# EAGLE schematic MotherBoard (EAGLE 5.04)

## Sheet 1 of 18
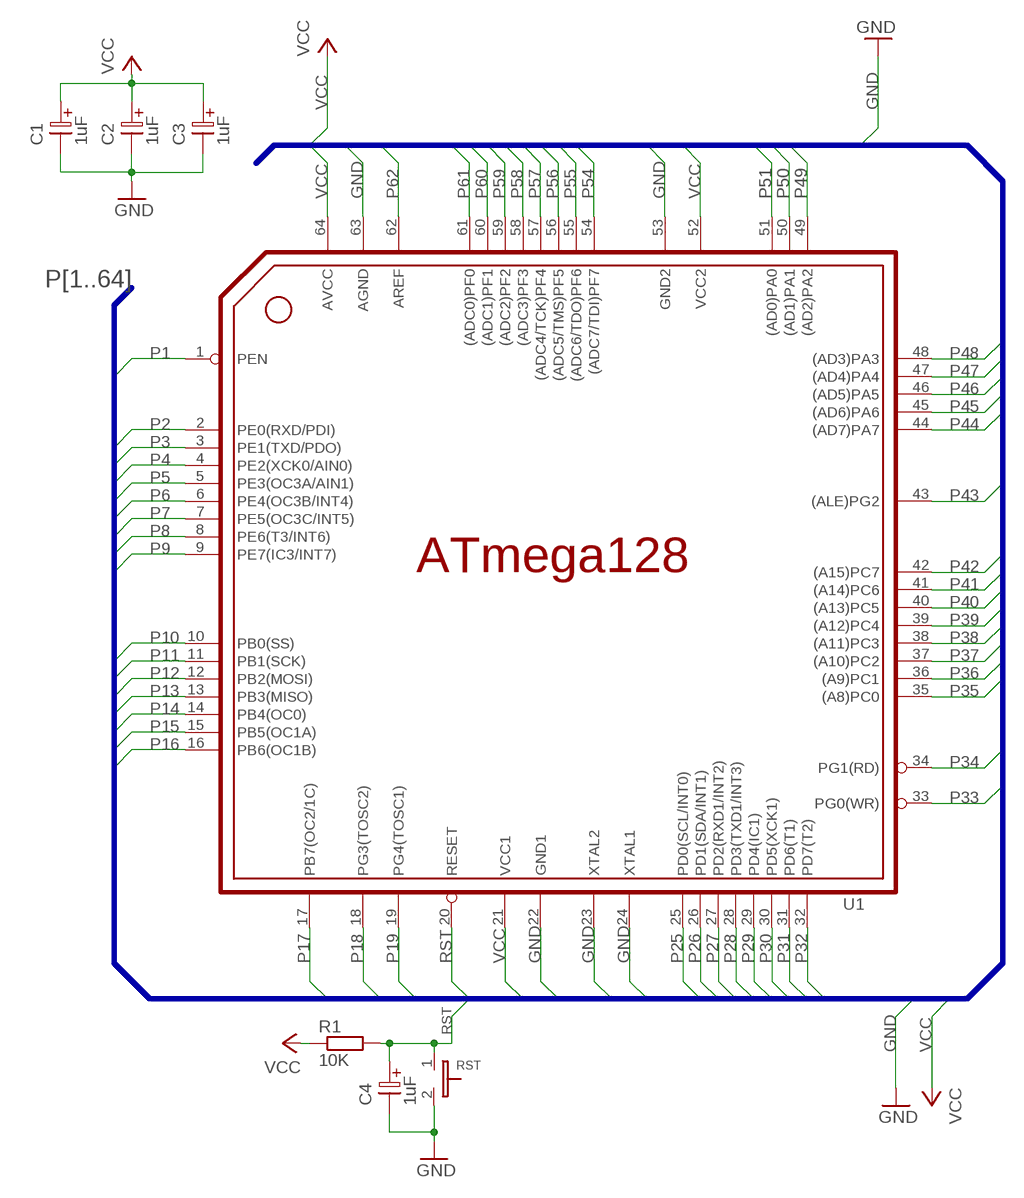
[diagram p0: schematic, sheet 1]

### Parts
C1  1uF  ELC2.5  [ELC2.5]
C2  1uF  ELC2.5  [ELC2.5]
C3  1uF  ELC2.5  [ELC2.5]
C4  1uF  ELC2.5  [ELC2.5]
R1  10K  R-5-10M  [R-10]
RST  TAC_SW_S  [SW]
U1  ATMEGA128_HOLDERH  [HEADER64PIN]

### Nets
GND: C1.2 C2.2 C3.2 C4.2 RST.2 U1.22(GND1) U1.23(XTAL2) U1.24(XTAL1) U1.53(GND2) U1.63(AGND) ; also sheet 2,3,4,5,6,7,8,10,11,12,13,14,15,16,17,18
P1: U1.1(PEN)
P2: U1.2(PE0(RXD/PDI)) ; also sheet 4,6,11,12
P3: U1.3(PE1(TXD/PDO)) ; also sheet 4,6,11,12
P4: U1.4(PE2(XCK0/AIN0)) ; also sheet 4,6,11,12
P5: U1.5(PE3(OC3A/AIN1)) ; also sheet 4,6,12,18
P6: U1.6(PE4(OC3B/INT4)) ; also sheet 4,5,12
P7: U1.7(PE5(OC3C/INT5)) ; also sheet 4,5,12
P8: U1.8(PE6(T3/INT6)) ; also sheet 4,5,12
P9: U1.9(PE7(IC3/INT7)) ; also sheet 4,5,12
P10: U1.10(PB0(SS)) ; also sheet 4,5,16
P11: U1.11(PB1(SCK)) ; also sheet 3,4,5,16
P12: U1.12(PB2(MOSI)) ; also sheet 3,4,5,16
P13: U1.13(PB3(MISO)) ; also sheet 3,4,5,16
P14: U1.14(PB4(OC0)) ; also sheet 4,5,13
P15: U1.15(PB5(OC1A)) ; also sheet 4,5,15
P16: U1.16(PB6(OC1B)) ; also sheet 4,5,18
P17: U1.17(PB7(OC2/1C)) ; also sheet 4,5,15
P18: U1.18(PG3(TOSC2))
P19: U1.19(PG4(TOSC1))
P25: U1.25(PD0(SCL/INT0)) ; also sheet 4,5,8,16
P26: U1.26(PD1(SDA/INT1)) ; also sheet 4,5,8
P27: U1.27(PD2(RXD1/INT2)) ; also sheet 4,5,6,8
P28: U1.28(PD3(TXD1/INT3)) ; also sheet 4,5,6,8
P29: U1.29(PD4(IC1)) ; also sheet 4,18
P30: U1.30(PD5(XCK1)) ; also sheet 4,18
P31: U1.31(PD6(T1)) ; also sheet 4,18
P32: U1.32(PD7(T2)) ; also sheet 4,18
P33: U1.33(PG0(WR)) ; also sheet 10,17
P34: U1.34(PG1(RD)) ; also sheet 10,17
P35: U1.35((A8)PC0) ; also sheet 4,10,13
P36: U1.36((A9)PC1) ; also sheet 4,10
P37: U1.37((A10)PC2) ; also sheet 4,7,10
P38: U1.38((A11)PC3) ; also sheet 4,7,10
P39: U1.39((A12)PC4) ; also sheet 4,7,9,10
P40: U1.40((A13)PC5) ; also sheet 4,7,9,10
P41: U1.41((A14)PC6) ; also sheet 4,7,9,10
P42: U1.42((A15)PC7) ; also sheet 4,7,9,10
P43: U1.43((ALE)PG2) ; also sheet 13,16
P44: U1.44((AD7)PA7) ; also sheet 4,7,9
P45: U1.45((AD6)PA6) ; also sheet 4,7,9
P46: U1.46((AD5)PA5) ; also sheet 4,7,9
P47: U1.47((AD4)PA4) ; also sheet 4,7,9,17
P48: U1.48((AD3)PA3) ; also sheet 4,7,9,17
P49: U1.49((AD2)PA2) ; also sheet 4,7,9,17
P50: U1.50((AD1)PA1) ; also sheet 4,6,7,9
P51: U1.51((AD0)PA0) ; also sheet 4,6,7,9
P54: U1.54((ADC7/TDI)PF7) ; also sheet 4,13
P55: U1.55((ADC6/TDO)PF6) ; also sheet 4,13
P56: U1.56((ADC5/TMS)PF5) ; also sheet 4,13
P57: U1.57((ADC4/TCK)PF4) ; also sheet 4,13
P58: U1.58((ADC3)PF3) ; also sheet 4,13
P59: U1.59((ADC2)PF2) ; also sheet 4,13
P60: U1.60((ADC1)PF1) ; also sheet 4,13
P61: U1.61((ADC0)PF0) ; also sheet 4,13
P62: U1.62(AREF) ; also sheet 13
RST: C4.1 R1.2 RST.1 U1.20(RESET) ; also sheet 3
VCC: C1.1 C2.1 C3.1 R1.1 U1.21(VCC1) U1.52(VCC2) U1.64(AVCC) ; also sheet 2,3,4,5,6,7,8,9,10,11,12,13,14,15,16,17,18

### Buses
P[1..64]

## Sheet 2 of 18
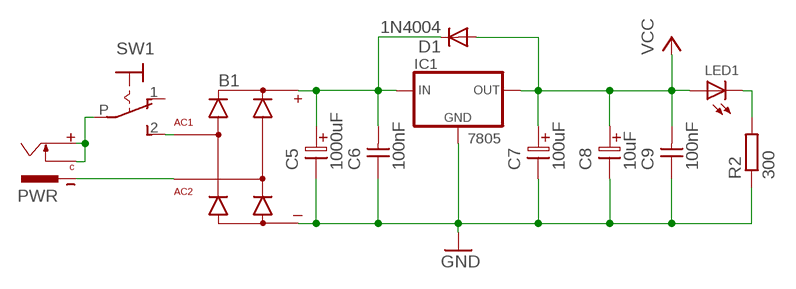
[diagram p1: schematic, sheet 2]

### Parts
B1  RB1A  [RB1A]
C5  1000uF  ELC5  [ELC5]
C6  100nF  CAP2.5  [CAP2.5]
C7  100uF  ELC2.5  [ELC2.5]
C8  10uF  ELC2.5  [ELC2.5]
C9  100nF  CAP2.5  [CAP2.5]
D1  1N4004  [DO41-10]
IC1  7805  78XXL  [78XXL]
LED1  LED3  [LED3MM]
PWR  DC-JACK.  [PW]
R2  300  RESISTOR-7M  [R-7]
SW1  POWER_SWSW  [SWITCH]

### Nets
GND: B1.- C5.2 C6.1 C7.2 C8.2 C9.1 IC1.GND R2.1 ; also sheet 1,3,4,5,6,7,8,10,11,12,13,14,15,16,17,18
N$2: B1.AC2 PWR.-
N$3: B1.+ C5.1 C6.2 D1.C IC1.IN
N$4: LED1.K(C) R2.2
N$189: B1.AC1 SW1.2
N$192: PWR.+ PWR.C SW1.P
VCC: C7.1 C8.1 C9.2 D1.A IC1.OUT LED1.A ; also sheet 1,3,4,5,6,7,8,9,10,11,12,13,14,15,16,17,18
Unconnected: SW1.1

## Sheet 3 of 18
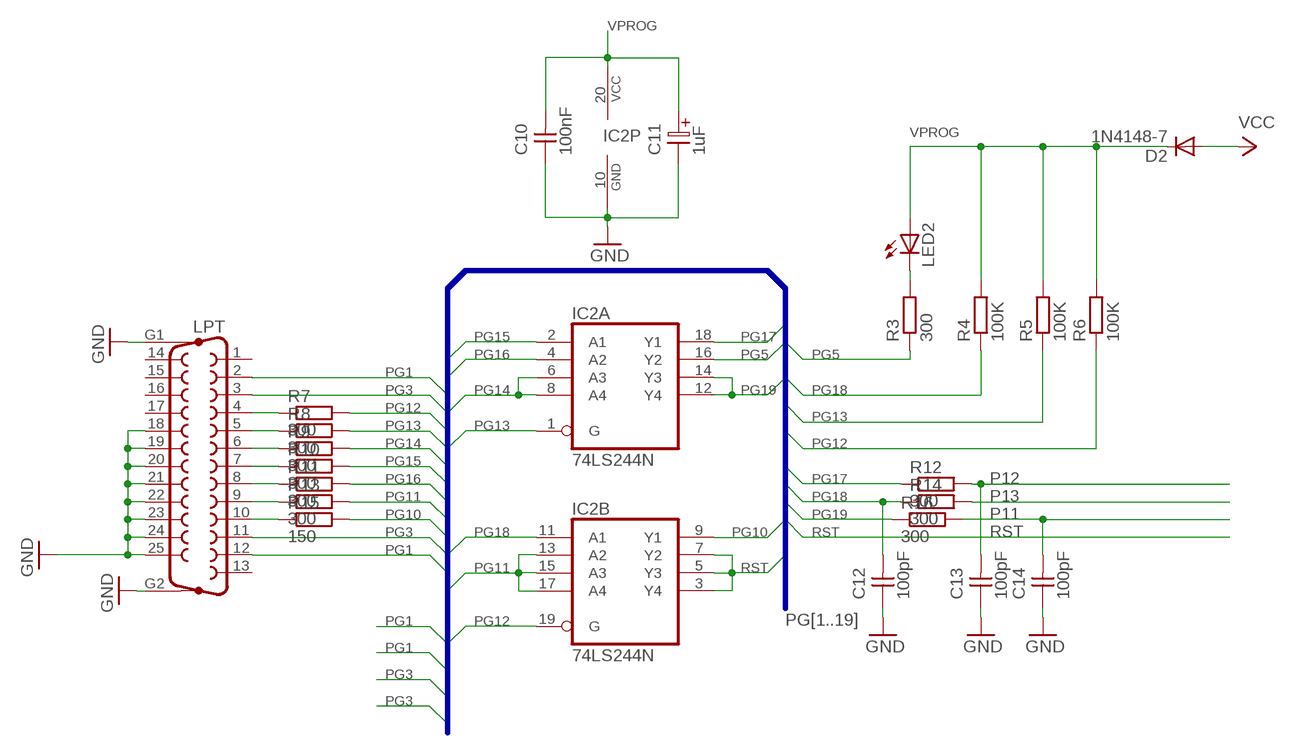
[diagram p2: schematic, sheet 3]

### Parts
C10  100nF  CAP2.5  [CAP2.5]
C11  1uF  ELC2.5  [ELC2.5]
C12  100pF  CAP2.5  [CAP2.5]
C13  100pF  CAP2.5  [CAP2.5]
C14  100pF  CAP2.5  [CAP2.5]
D2  1N4148-7  [DO35-7]
IC2  74LS244N  [DIL20]
LED2  LED3MM  [LED3MM]
LPT  F25HP  [F25HP]
R3  300  R-5-10M  [R-10]
R4  100K  R-5-10M  [R-10]
R5  100K  R-5-10M  [R-10]
R6  100K  R-5-10M  [R-10]
R7  300  R-5-10M  [R-10]
R8  300  R-5-10M  [R-10]
R9  300  R-5-10M  [R-10]
R10  300  R-5-10M  [R-10]
R11  300  R-5-10M  [R-10]
R12  300  R-5-10M  [R-10]
R13  300  R-5-10M  [R-10]
R14  300  R-5-10M  [R-10]
R15  150  R-5-10M  [R-10]
R16  300  R-5-10M  [R-10]

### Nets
GND: C10.1 C11.2 C12.1 C13.1 C14.1 IC2.10(P:GND) LPT.18 LPT.19 LPT.20 LPT.21 LPT.22 LPT.23 LPT.24 LPT.25 LPT.G1 LPT.G2 ; also sheet 1,2,4,5,6,7,8,10,11,12,13,14,15,16,17,18
N$5: LED2.K(C) R3.2
N$265: LPT.4 R7.1
N$266: LPT.5 R8.1
N$278: LPT.6 R9.1
N$279: LPT.7 R10.1
N$280: LPT.8 R11.1
N$281: LPT.9 R13.1
N$282: LPT.10 R15.1
P11: C14.2 R16.2 ; also sheet 1,4,5,16
P12: C13.2 R12.2 ; also sheet 1,4,5,16
P13: R14.2 ; also sheet 1,4,5,16
PG1: LPT.2 LPT.12
PG3: LPT.3 LPT.11
PG5: IC2.16(A:Y2) R3.1
PG10: IC2.9(B:Y1) R15.2
PG11: IC2.13(B:A2) IC2.15(B:A3) IC2.17(B:A4) R13.2
PG12: IC2.19(B:G) R6.1 R7.2
PG13: IC2.1(A:G) R5.1 R8.2
PG14: IC2.6(A:A3) IC2.8(A:A4) R9.2
PG15: IC2.2(A:A1) R10.2
PG16: IC2.4(A:A2) R11.2
PG17: IC2.18(A:Y1) R12.1
PG18: C12.2 IC2.11(B:A1) R4.1 R14.1
PG19: IC2.12(A:Y4) IC2.14(A:Y3) R16.1
RST: IC2.3(B:Y4) IC2.5(B:Y3) IC2.7(B:Y2) ; also sheet 1
VCC: D2.A ; also sheet 1,2,4,5,6,7,8,9,10,11,12,13,14,15,16,17,18
VPROG: C10.2 C11.1 D2.C IC2.20(P:VCC) LED2.A R4.2 R5.2 R6.2
Unconnected: LPT.1 LPT.13 LPT.14 LPT.15 LPT.16 LPT.17

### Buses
PG[1..19]

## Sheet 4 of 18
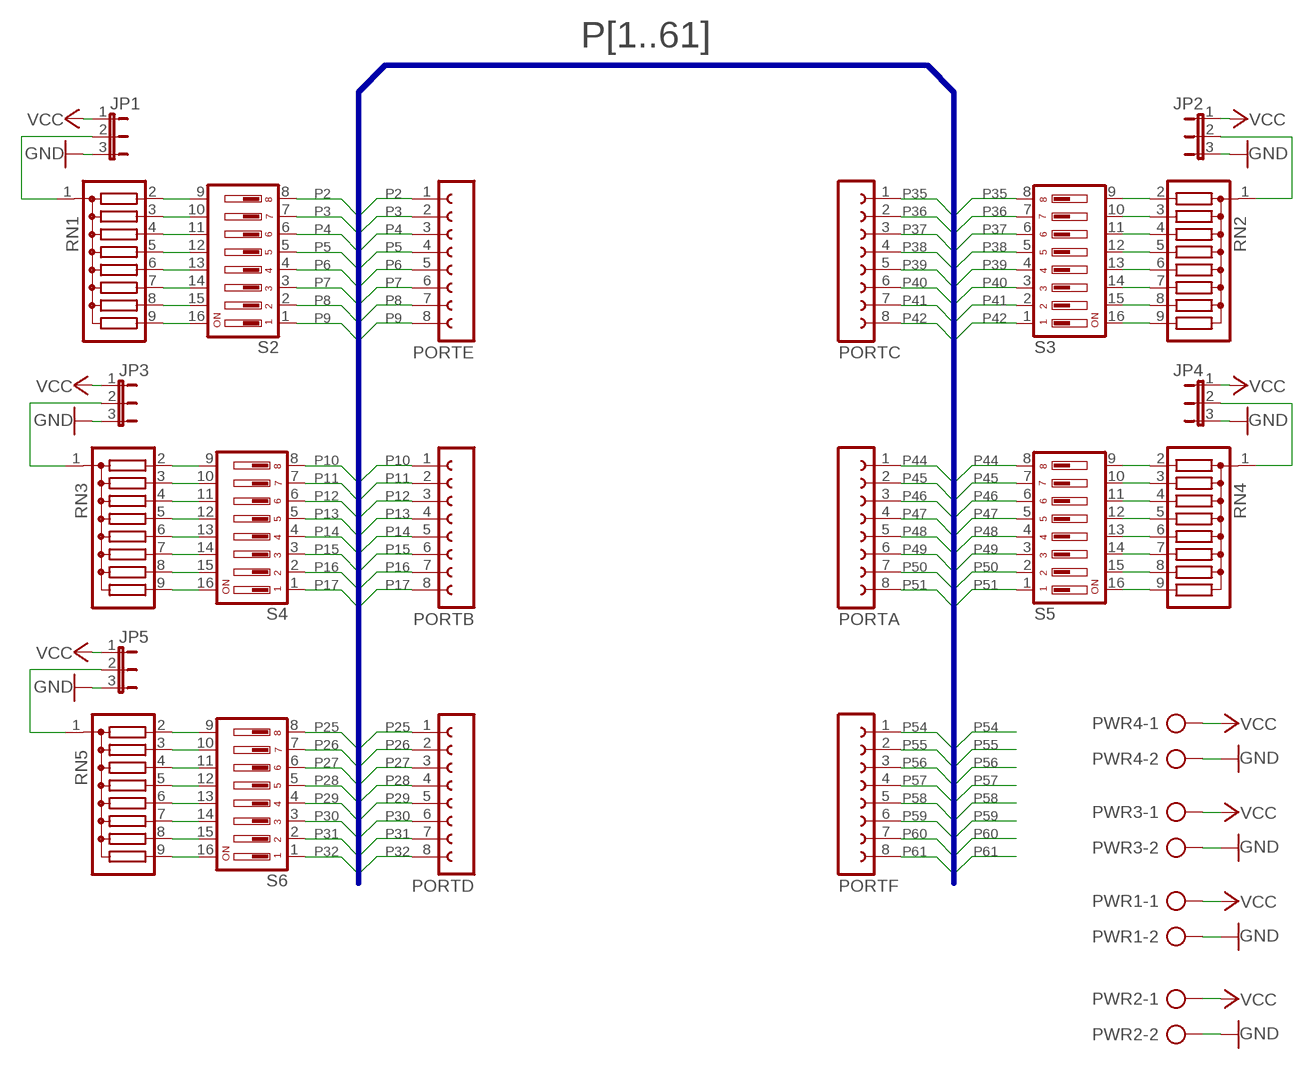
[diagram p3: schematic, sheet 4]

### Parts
JP1  JP2E  [JP2]
JP2  JP2E  [JP2]
JP3  JP2E  [JP2]
JP4  JP2E  [JP2]
JP5  JP2E  [JP2]
PORTA  FE08-1  [FE08]
PORTB  FE08-1  [FE08]
PORTC  FE08-1  [FE08]
PORTD  FE08-1  [FE08]
PORTE  FE08-1  [FE08]
PORTF  FE08-1  [FE08]
PWR1  AK500/2  [AK500/2]
PWR2  AK500/2  [AK500/2]
PWR3  AK500/2  [AK500/2]
PWR4  AK500/2  [AK500/2]
RN1  G08R  [SIL9]
RN2  G08R  [SIL9]
RN3  G08R  [SIL9]
RN4  G08R  [SIL9]
RN5  G08R  [SIL9]
S2  DIP08YL  [DIP08YL]
S3  DIP08YL  [DIP08YL]
S4  DIP08YL  [DIP08YL]
S5  DIP08YL  [DIP08YL]
S6  DIP08YL  [DIP08YL]

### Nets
GND: JP1.3 JP2.3 JP3.3 JP4.3 JP5.3 PWR1.2 PWR2.2 PWR3.2 PWR4.2 ; also sheet 1,2,3,5,6,7,8,10,11,12,13,14,15,16,17,18
N$6: JP1.2 RN1.1
N$7: JP3.2 RN3.1
N$8: RN3.2 S4.9
N$12: RN1.2 S2.9
N$13: RN1.3 S2.10
N$14: RN1.4 S2.11
N$15: RN1.5 S2.12
N$16: RN1.6 S2.13
N$17: RN1.7 S2.14
N$18: RN1.8 S2.15
N$19: RN1.9 S2.16
N$20: RN3.3 S4.10
N$21: RN3.4 S4.11
N$22: RN3.5 S4.12
N$23: RN3.6 S4.13
N$24: RN3.7 S4.14
N$25: RN3.8 S4.15
N$26: RN3.9 S4.16
N$27: JP5.2 RN5.1
N$28: RN5.2 S6.9
N$29: RN5.3 S6.10
N$30: RN5.4 S6.11
N$31: RN5.5 S6.12
N$32: RN5.6 S6.13
N$33: RN5.7 S6.14
N$34: RN5.8 S6.15
N$35: RN5.9 S6.16
N$42: JP4.2 RN4.1
N$43: RN4.2 S5.9
N$44: RN4.3 S5.10
N$45: RN4.4 S5.11
N$46: RN4.5 S5.12
N$47: RN4.6 S5.13
N$48: RN4.7 S5.14
N$49: RN4.8 S5.15
N$50: RN4.9 S5.16
N$51: JP2.2 RN2.1
N$52: RN2.2 S3.9
N$53: RN2.3 S3.10
N$54: RN2.4 S3.11
N$55: RN2.5 S3.12
N$56: RN2.6 S3.13
N$57: RN2.7 S3.14
N$58: RN2.8 S3.15
N$59: RN2.9 S3.16
P2: PORTE.1 S2.8 ; also sheet 1,6,11,12
P3: PORTE.2 S2.7 ; also sheet 1,6,11,12
P4: PORTE.3 S2.6 ; also sheet 1,6,11,12
P5: PORTE.4 S2.5 ; also sheet 1,6,12,18
P6: PORTE.5 S2.4 ; also sheet 1,5,12
P7: PORTE.6 S2.3 ; also sheet 1,5,12
P8: PORTE.7 S2.2 ; also sheet 1,5,12
P9: PORTE.8 S2.1 ; also sheet 1,5,12
P10: PORTB.1 S4.8 ; also sheet 1,5,16
P11: PORTB.2 S4.7 ; also sheet 1,3,5,16
P12: PORTB.3 S4.6 ; also sheet 1,3,5,16
P13: PORTB.4 S4.5 ; also sheet 1,3,5,16
P14: PORTB.5 S4.4 ; also sheet 1,5,13
P15: PORTB.6 S4.3 ; also sheet 1,5,15
P16: PORTB.7 S4.2 ; also sheet 1,5,18
P17: PORTB.8 S4.1 ; also sheet 1,5,15
P25: PORTD.1 S6.8 ; also sheet 1,5,8,16
P26: PORTD.2 S6.7 ; also sheet 1,5,8
P27: PORTD.3 S6.6 ; also sheet 1,5,6,8
P28: PORTD.4 S6.5 ; also sheet 1,5,6,8
P29: PORTD.5 S6.4 ; also sheet 1,18
P30: PORTD.6 S6.3 ; also sheet 1,18
P31: PORTD.7 S6.2 ; also sheet 1,18
P32: PORTD.8 S6.1 ; also sheet 1,18
P35: PORTC.1 S3.8 ; also sheet 1,10,13
P36: PORTC.2 S3.7 ; also sheet 1,10
P37: PORTC.3 S3.6 ; also sheet 1,7,10
P38: PORTC.4 S3.5 ; also sheet 1,7,10
P39: PORTC.5 S3.4 ; also sheet 1,7,9,10
P40: PORTC.6 S3.3 ; also sheet 1,7,9,10
P41: PORTC.7 S3.2 ; also sheet 1,7,9,10
P42: PORTC.8 S3.1 ; also sheet 1,7,9,10
P44: PORTA.1 S5.8 ; also sheet 1,7,9
P45: PORTA.2 S5.7 ; also sheet 1,7,9
P46: PORTA.3 S5.6 ; also sheet 1,7,9
P47: PORTA.4 S5.5 ; also sheet 1,7,9,17
P48: PORTA.5 S5.4 ; also sheet 1,7,9,17
P49: PORTA.6 S5.3 ; also sheet 1,7,9,17
P50: PORTA.7 S5.2 ; also sheet 1,6,7,9
P51: PORTA.8 S5.1 ; also sheet 1,6,7,9
P54: PORTF.1 ; also sheet 1,13
P55: PORTF.2 ; also sheet 1,13
P56: PORTF.3 ; also sheet 1,13
P57: PORTF.4 ; also sheet 1,13
P58: PORTF.5 ; also sheet 1,13
P59: PORTF.6 ; also sheet 1,13
P60: PORTF.7 ; also sheet 1,13
P61: PORTF.8 ; also sheet 1,13
VCC: JP1.1 JP2.1 JP3.1 JP4.1 JP5.1 PWR1.1 PWR2.1 PWR3.1 PWR4.1 ; also sheet 1,2,3,5,6,7,8,9,10,11,12,13,14,15,16,17,18

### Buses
P[1..61]

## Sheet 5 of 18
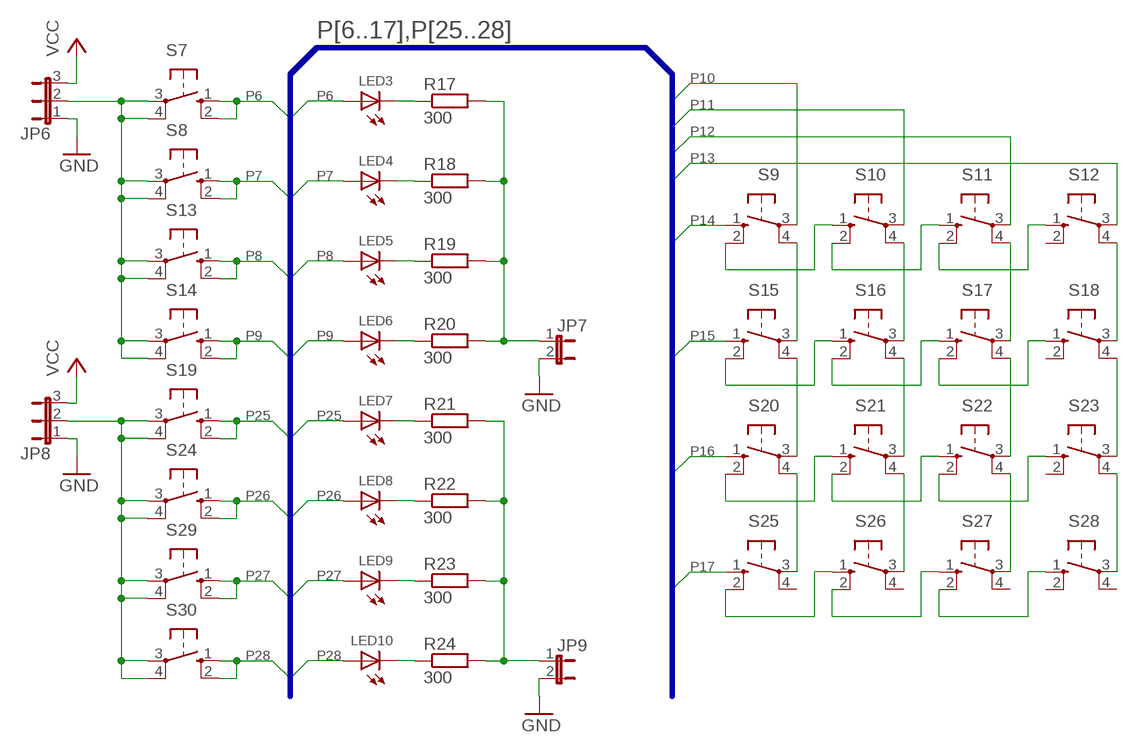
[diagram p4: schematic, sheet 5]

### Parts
JP6  JP2E  [JP2]
JP7  JP1EY  [JP1Y]
JP8  JP2E  [JP2]
JP9  JP1EY  [JP1Y]
LED3  LED5  [LED5MM]
LED4  LED5  [LED5MM]
LED5  LED5  [LED5MM]
LED6  LED5  [LED5MM]
LED7  LED5  [LED5MM]
LED8  LED5  [LED5MM]
LED9  LED5  [LED5MM]
LED10  LED5  [LED5MM]
R17  300  RESISTOR-10M  [R-10]
R18  300  RESISTOR-10M  [R-10]
R19  300  RESISTOR-10M  [R-10]
R20  300  RESISTOR-10M  [R-10]
R21  300  RESISTOR-8M  [R-8]
R22  300  RESISTOR-8M  [R-8]
R23  300  RESISTOR-8M  [R-8]
R24  300  RESISTOR-8M  [R-8]
S7  10-XX  [B3F-10XX]
S8  10-XX  [B3F-10XX]
S9  TAC_SW_B  [B3F-40XX]
S10  TAC_SW_B  [B3F-40XX]
S11  TAC_SW_B  [B3F-40XX]
S12  TAC_SW_B  [B3F-40XX]
S13  10-XX  [B3F-10XX]
S14  10-XX  [B3F-10XX]
S15  TAC_SW_B  [B3F-40XX]
S16  TAC_SW_B  [B3F-40XX]
S17  TAC_SW_B  [B3F-40XX]
S18  TAC_SW_B  [B3F-40XX]
S19  10-XX  [B3F-10XX]
S20  TAC_SW_B  [B3F-40XX]
S21  TAC_SW_B  [B3F-40XX]
S22  TAC_SW_B  [B3F-40XX]
S23  TAC_SW_B  [B3F-40XX]
S24  10-XX  [B3F-10XX]
S25  TAC_SW_B  [B3F-40XX]
S26  TAC_SW_B  [B3F-40XX]
S27  TAC_SW_B  [B3F-40XX]
S28  TAC_SW_B  [B3F-40XX]
S29  10-XX  [B3F-10XX]
S30  10-XX  [B3F-10XX]

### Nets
GND: JP6.1 JP7.2 JP8.1 JP9.2 ; also sheet 1,2,3,4,6,7,8,10,11,12,13,14,15,16,17,18
N$9: JP6.2 S7.3(P) S7.4(P1) S8.3(P) S8.4(P1) S13.3(P) S13.4(P1) S14.3(P) S14.4(P1)
N$11: JP8.2 S19.3(P) S19.4(P1) S24.3(P) S24.4(P1) S29.3(P) S29.4(P1) S30.3(P) S30.4(P1)
N$36: S9.2(S1) S10.1(S)
N$37: S10.2(S1) S11.1(S)
N$38: S11.2(S1) S12.1(S)
N$39: S20.2(S1) S21.1(S)
N$40: S21.2(S1) S22.1(S)
N$41: S22.2(S1) S23.1(S)
N$60: S15.2(S1) S16.1(S)
N$61: S16.2(S1) S17.1(S)
N$62: S17.2(S1) S18.1(S)
N$65: S25.2(S1) S26.1(S)
N$66: S26.2(S1) S27.1(S)
N$67: S9.4(P1) S15.3(P)
N$68: S10.4(P1) S16.3(P)
N$69: S11.4(P1) S17.3(P)
N$70: S12.4(P1) S18.3(P)
N$71: S27.2(S1) S28.1(S)
N$73: S20.4(P1) S25.3(P)
N$74: S21.4(P1) S26.3(P)
N$75: S22.4(P1) S27.3(P)
N$76: S23.4(P1) S28.3(P)
N$77: S15.4(P1) S20.3(P)
N$78: S16.4(P1) S21.3(P)
N$79: S17.4(P1) S22.3(P)
N$80: S18.4(P1) S23.3(P)
N$138: LED3.K(C) R17.1
N$139: LED5.K(C) R19.1
N$140: LED6.K(C) R20.1
N$141: LED7.K(C) R21.1
N$142: LED8.K(C) R22.1
N$143: LED9.K(C) R23.1
N$144: LED10.K(C) R24.1
N$145: LED4.K(C) R18.1
N$276: JP7.1 R17.2 R18.2 R19.2 R20.2
N$277: JP9.1 R21.2 R22.2 R23.2 R24.2
P6: LED3.A S7.1(S) S7.2(S1) ; also sheet 1,4,12
P7: LED4.A S8.1(S) S8.2(S1) ; also sheet 1,4,12
P8: LED5.A S13.1(S) S13.2(S1) ; also sheet 1,4,12
P9: LED6.A S14.1(S) S14.2(S1) ; also sheet 1,4,12
P10: S9.3(P) ; also sheet 1,4,16
P11: S10.3(P) ; also sheet 1,3,4,16
P12: S11.3(P) ; also sheet 1,3,4,16
P13: S12.3(P) ; also sheet 1,3,4,16
P14: S9.1(S) ; also sheet 1,4,13
P15: S15.1(S) ; also sheet 1,4,15
P16: S20.1(S) ; also sheet 1,4,18
P17: S25.1(S) ; also sheet 1,4,15
P25: LED7.A S19.1(S) S19.2(S1) ; also sheet 1,4,8,16
P26: LED8.A S24.1(S) S24.2(S1) ; also sheet 1,4,8
P27: LED9.A S29.1(S) S29.2(S1) ; also sheet 1,4,6,8
P28: LED10.A S30.1(S) S30.2(S1) ; also sheet 1,4,6,8
VCC: JP6.3 JP8.3 ; also sheet 1,2,3,4,6,7,8,9,10,11,12,13,14,15,16,17,18
Unconnected: S12.2(S1) S18.2(S1) S23.2(S1) S25.4(P1) S26.4(P1) S27.4(P1) S28.2(S1) S28.4(P1)

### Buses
P[6..17],P[25..28]

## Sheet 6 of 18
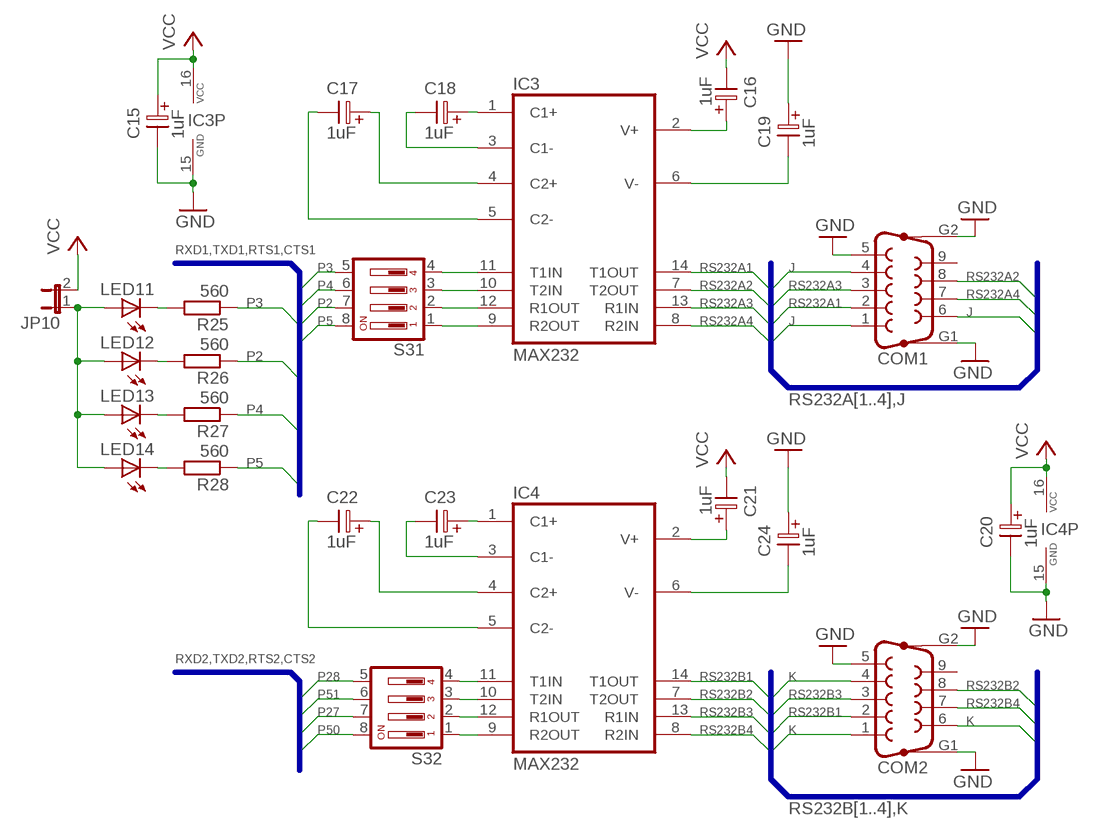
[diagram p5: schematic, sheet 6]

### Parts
C15  1uF  ELC2.5  [ELC2.5]
C16  1uF  ELC2.5  [ELC2.5]
C17  1uF  ELC2.5  [ELC2.5]
C18  1uF  ELC2.5  [ELC2.5]
C19  1uF  ELC2.5  [ELC2.5]
C20  1uF  ELC2.5  [ELC2.5]
C21  1uF  ELC2.5  [ELC2.5]
C22  1uF  ELC2.5  [ELC2.5]
C23  1uF  ELC2.5  [ELC2.5]
C24  1uF  ELC2.5  [ELC2.5]
COM1  F09HP  [F09HP]
COM2  F09HP  [F09HP]
IC3  MAX232  [DIL16L]
IC4  MAX232  [DIL16L]
JP10  JP1EY  [JP1Y]
LED11  LED3MM  [LED3MM]
LED12  LED3MM  [LED3MM]
LED13  LED3MM  [LED3MM]
LED14  LED3MM  [LED3MM]
R25  560  R-5-10M  [R-10]
R26  560  R-5-10M  [R-10]
R27  560  R-5-10M  [R-10]
R28  560  R-5-10M  [R-10]
S31  DIP04YL  [DIP04YL]
S32  DIP04YL  [DIP04YL]

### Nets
GND: C15.2 C19.1 C20.2 C24.1 COM1.5 COM1.G1 COM1.G2 COM2.5 COM2.G1 COM2.G2 IC3.15(GND) IC4.15(GND) ; also sheet 1,2,3,4,5,7,8,10,11,12,13,14,15,16,17,18
J: COM1.1 COM1.4 COM1.6
K: COM2.1 COM2.4 COM2.6
N$10: C18.1 IC3.1(C1+)
N$63: C18.2 IC3.3(C1-)
N$64: C17.1 IC3.4(C2+)
N$72: C17.2 IC3.5(C2-)
N$81: C19.2 IC3.6(V-)
N$82: C16.1 IC3.2(V+)
N$83: IC3.9(R2OUT) S31.1
N$84: IC3.12(R1OUT) S31.2
N$85: IC3.10(T2IN) S31.3
N$86: IC3.11(T1IN) S31.4
N$87: C23.1 IC4.1(C1+)
N$88: C23.2 IC4.3(C1-)
N$89: C22.1 IC4.4(C2+)
N$90: C22.2 IC4.5(C2-)
N$91: C24.2 IC4.6(V-)
N$92: C21.1 IC4.2(V+)
N$93: IC4.9(R2OUT) S32.1
N$94: IC4.12(R1OUT) S32.2
N$95: IC4.10(T2IN) S32.3
N$96: IC4.11(T1IN) S32.4
N$97: LED11.K(C) R25.2
N$230: JP10.1 LED11.A LED12.A LED13.A LED14.A
N$269: LED12.K(C) R26.2
N$270: LED13.K(C) R27.2
N$271: LED14.K(C) R28.2
P2: R26.1 S31.7 ; also sheet 1,4,11,12
P3: R25.1 S31.5 ; also sheet 1,4,11,12
P4: R27.1 S31.6 ; also sheet 1,4,11,12
P5: R28.1 S31.8 ; also sheet 1,4,12,18
P27: S32.7 ; also sheet 1,4,5,8
P28: S32.5 ; also sheet 1,4,5,8
P50: S32.8 ; also sheet 1,4,7,9
P51: S32.6 ; also sheet 1,4,7,9
RS232A1: COM1.2 IC3.14(T1OUT)
RS232A2: COM1.8 IC3.7(T2OUT)
RS232A3: COM1.3 IC3.13(R1IN)
RS232A4: COM1.7 IC3.8(R2IN)
RS232B1: COM2.2 IC4.14(T1OUT)
RS232B2: COM2.8 IC4.7(T2OUT)
RS232B3: COM2.3 IC4.13(R1IN)
RS232B4: COM2.7 IC4.8(R2IN)
VCC: C15.1 C16.2 C20.1 C21.2 IC3.16(VCC) IC4.16(VCC) JP10.2 ; also sheet 1,2,3,4,5,7,8,9,10,11,12,13,14,15,16,17,18
Unconnected: COM1.9 COM2.9

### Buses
RS232A[1..4],J
RXD1,TXD1,RTS1,CTS1
RS232B[1..4],K
RXD2,TXD2,RTS2,CTS2

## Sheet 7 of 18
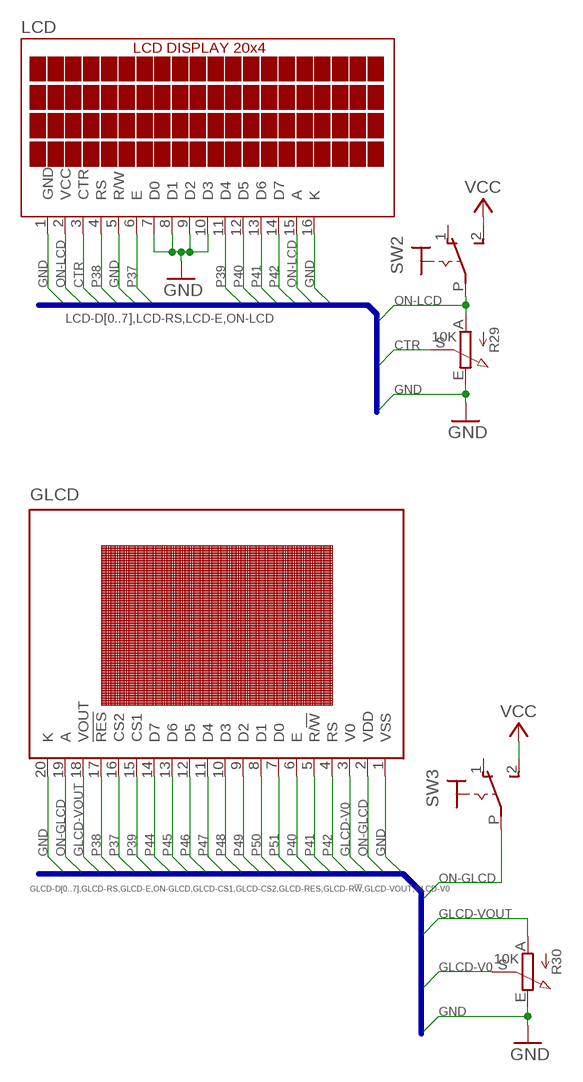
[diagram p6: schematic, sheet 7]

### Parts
GLCD  LCD128X64  [LCD128X64]
LCD  LCD20X4  [LCD20X4]
R29  10K  POT  [POT]
R30  10K  POT  [POT]
SW2  POWER_SW3  [ON_OFF]
SW3  POWER_SW3  [ON_OFF]

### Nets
CTR: LCD.3(CTR) R29.S
GLCD-V0: GLCD.3(V0) R30.S
GLCD-VOUT: GLCD.18(VOUT) R30.A
GND: GLCD.1(VSS) GLCD.20(K) LCD.1(GND) LCD.5(R/W) LCD.7(D0) LCD.8(D1) LCD.9(D2) LCD.10(D3) LCD.16(K) R29.E R30.E ; also sheet 1,2,3,4,5,6,8,10,11,12,13,14,15,16,17,18
ON-GLCD: GLCD.2(VDD) GLCD.19(A) SW3.P
ON-LCD: LCD.2(VCC) LCD.15(A) R29.A SW2.P
P37: GLCD.16(CS2) LCD.6(E) ; also sheet 1,4,10
P38: GLCD.17(!RES) LCD.4(RS) ; also sheet 1,4,10
P39: GLCD.15(CS1) LCD.11(D4) ; also sheet 1,4,9,10
P40: GLCD.6(E) LCD.12(D5) ; also sheet 1,4,9,10
P41: GLCD.5(R/!W) LCD.13(D6) ; also sheet 1,4,9,10
P42: GLCD.4(RS) LCD.14(D7) ; also sheet 1,4,9,10
P44: GLCD.14(D7) ; also sheet 1,4,9
P45: GLCD.13(D6) ; also sheet 1,4,9
P46: GLCD.12(D5) ; also sheet 1,4,9
P47: GLCD.11(D4) ; also sheet 1,4,9,17
P48: GLCD.10(D3) ; also sheet 1,4,9,17
P49: GLCD.9(D2) ; also sheet 1,4,9,17
P50: GLCD.8(D1) ; also sheet 1,4,6,9
P51: GLCD.7(D0) ; also sheet 1,4,6,9
VCC: SW2.2 SW3.2 ; also sheet 1,2,3,4,5,6,8,9,10,11,12,13,14,15,16,17,18
Unconnected: SW2.1 SW3.1

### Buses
LCD-D[0..7],LCD-RS,LCD-E,ON-LCD
GLCD-D[0..7],GLCD-RS,GLCD-E,ON-GLCD,GLCD-CS1,GLCD-CS2,GLCD-RES,GLCD-R!W,GLCD-VOUT,GLCD-V0

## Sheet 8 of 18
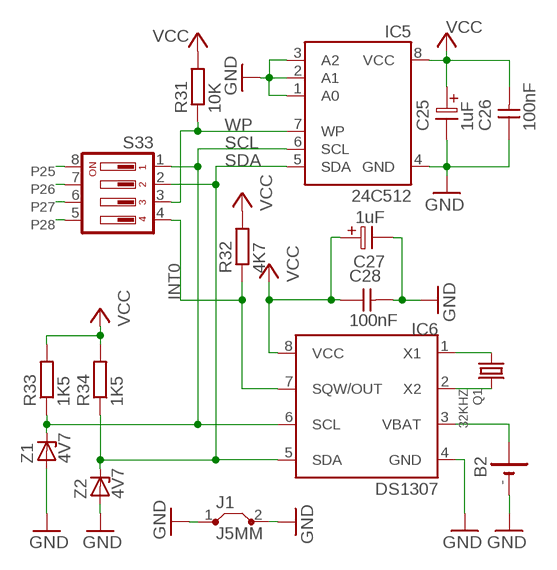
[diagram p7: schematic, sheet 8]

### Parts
B2  BATTB  [BATT]
C25  1uF  ELC2.5  [ELC2.5]
C26  100nF  CAP2.5  [CAP2.5]
C27  1uF  ELC2.5  [ELC2.5]
C28  100nF  CAP2.5  [CAP2.5]
IC5  24C512  AT24CP  [DIL8L]
IC6  DS1307  DS1307L  [DIL8L]
J1  J5MM  [05]
Q1  32KHZ  CRYSTALTC  [TC26]
R31  10K  RESISTOR-10M  [R-10]
R32  4K7  RESISTOR-10M  [R-10]
R33  1K5  RESISTOR-10M  [R-10]
R34  1K5  RESISTOR-10M  [R-10]
S33  DIP04YL  [DIP04YL]
Z1  4V7  ZENER7  [DO35-7B]
Z2  4V7  ZENER7  [DO35-7B]

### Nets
GND: B2.- C25.2 C26.1 C27.2 C28.2 IC5.1(A0) IC5.2(A1) IC5.3(A2) IC5.4(GND) IC6.4(GND) J1.1 J1.2 Z1.A Z2.A ; also sheet 1,2,3,4,5,6,7,10,11,12,13,14,15,16,17,18
INT0: IC6.7(SQW/OUT) R32.1 S33.4
N$131: IC6.2(X2) Q1.2
N$132: IC6.1(X1) Q1.1
P25: S33.8 ; also sheet 1,4,5,16
P26: S33.7 ; also sheet 1,4,5
P27: S33.6 ; also sheet 1,4,5,6
P28: S33.5 ; also sheet 1,4,5,6
SCL: IC5.6(SCL) IC6.6(SCL) R33.1 S33.1 Z1.C
SDA: IC5.5(SDA) IC6.5(SDA) R34.1 S33.2 Z2.C
VBAT1: B2.+ IC6.3(VBAT)
VCC: C25.1 C26.2 C27.1 C28.1 IC5.8(VCC) IC6.8(VCC) R31.2 R32.2 R33.2 R34.2 ; also sheet 1,2,3,4,5,6,7,9,10,11,12,13,14,15,16,17,18
WP: IC5.7(WP) R31.1 S33.3

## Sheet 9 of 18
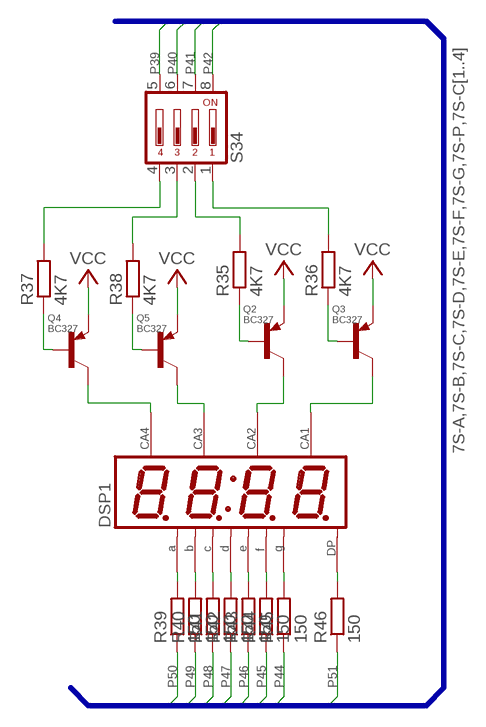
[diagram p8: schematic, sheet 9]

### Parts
DSP1  DISPLAY-Q0.56'  [DISPLAY-Q0.56]
Q2  BC327  BC327L  [TO92L]
Q3  BC327  BC327L  [TO92L]
Q4  BC327  BC327L  [TO92L]
Q5  BC327  BC327L  [TO92L]
R35  4K7  RESISTOR-10M  [R-10]
R36  4K7  RESISTOR-10M  [R-10]
R37  4K7  RESISTOR-10M  [R-10]
R38  4K7  RESISTOR-10M  [R-10]
R39  150  RESISTOR-10M  [R-10]
R40  150  RESISTOR-15M  [R-15]
R41  150  RESISTOR-10M  [R-10]
R42  150  RESISTOR-10M  [R-10]
R43  150  RESISTOR-10M  [R-10]
R44  150  RESISTOR-10M  [R-10]
R45  150  RESISTOR-10M  [R-10]
R46  150  RESISTOR-10M  [R-10]
S34  DIP04YL  [DIP04YL]

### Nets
N$106: DSP1.11(A) R39.2
N$110: DSP1.7(B) R40.2
N$111: DSP1.4(C) R41.2
N$112: DSP1.2(D) R42.2
N$113: DSP1.1(E) R43.2
N$114: DSP1.10(F) R44.2
N$115: DSP1.5(G) R45.2
N$116: DSP1.3(DP) R46.2
N$117: Q3.2(B) R36.1
N$118: Q2.2(B) R35.1
N$119: Q5.2(B) R38.1
N$120: Q4.2(B) R37.1
N$121: R37.2 S34.4
N$122: R38.2 S34.3
N$123: R35.2 S34.2
N$124: R36.2 S34.1
N$125: DSP1.6(CA1) Q3.3(C)
N$126: DSP1.8(CA2) Q2.3(C)
N$127: DSP1.9(CA3) Q5.3(C)
N$128: DSP1.12(CA4) Q4.3(C)
P39: S34.5 ; also sheet 1,4,7,10
P40: S34.6 ; also sheet 1,4,7,10
P41: S34.7 ; also sheet 1,4,7,10
P42: S34.8 ; also sheet 1,4,7,10
P44: R45.1 ; also sheet 1,4,7
P45: R44.1 ; also sheet 1,4,7
P46: R43.1 ; also sheet 1,4,7
P47: R42.1 ; also sheet 1,4,7,17
P48: R41.1 ; also sheet 1,4,7,17
P49: R40.1 ; also sheet 1,4,7,17
P50: R39.1 ; also sheet 1,4,6,7
P51: R46.1 ; also sheet 1,4,6,7
VCC: Q2.1(E) Q3.1(E) Q4.1(E) Q5.1(E) ; also sheet 1,2,3,4,5,6,7,8,10,11,12,13,14,15,16,17,18

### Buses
7S-A,7S-B,7S-C,7S-D,7S-E,7S-F,7S-G,7S-P,7S-C[1..4]

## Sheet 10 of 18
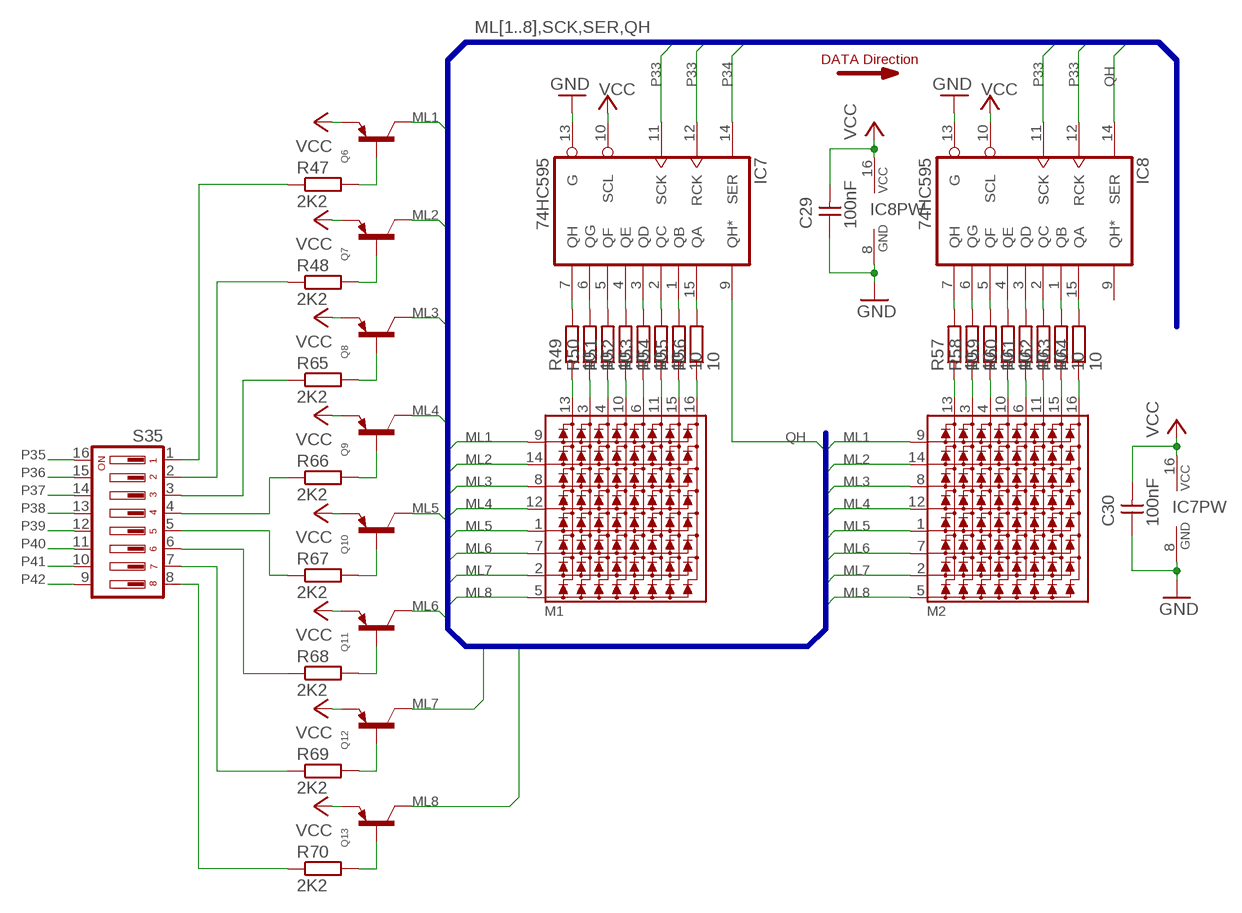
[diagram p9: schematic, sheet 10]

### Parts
C29  100nF  CAP2.5  [CAP2.5]
C30  100nF  CAP2.5  [CAP2.5]
IC7  74HC595  74HC595L  [DIL16L]
IC8  74HC595  74HC595L  [DIL16L]
M1  8X8MATRIX-3MM  [8X8MATRIX-3MM]
M2  8X8MATRIX-3MM  [8X8MATRIX-3MM]
Q6  BC327L  [TO92L]
Q7  BC327L  [TO92L]
Q8  BC327L  [TO92L]
Q9  BC327L  [TO92L]
Q10  BC327L  [TO92L]
Q11  BC327L  [TO92L]
Q12  BC327L  [TO92L]
Q13  BC327L  [TO92L]
R47  2K2  RESISTOR-15M  [R-15]
R48  2K2  RESISTOR-15M  [R-15]
R49  10  RESISTOR-10M  [R-10]
R50  10  RESISTOR-10M  [R-10]
R51  10  RESISTOR-10M  [R-10]
R52  10  RESISTOR-10M  [R-10]
R53  10  RESISTOR-10M  [R-10]
R54  10  RESISTOR-10M  [R-10]
R55  10  RESISTOR-15M  [R-15]
R56  10  RESISTOR-8M  [R-8]
R57  10  RESISTOR-10M  [R-10]
R58  10  RESISTOR-10M  [R-10]
R59  10  RESISTOR-10M  [R-10]
R60  10  RESISTOR-15M  [R-15]
R61  10  RESISTOR-10M  [R-10]
R62  10  RESISTOR-13M  [R-13]
R63  10  RESISTOR-10M  [R-10]
R64  10  RESISTOR-15M  [R-15]
R65  2K2  RESISTOR-15M  [R-15]
R66  2K2  RESISTOR-15M  [R-15]
R67  2K2  RESISTOR-15M  [R-15]
R68  2K2  RESISTOR-15M  [R-15]
R69  2K2  RESISTOR-15M  [R-15]
R70  2K2  RESISTOR-15M  [R-15]
S35  DIP08YL  [DIP08YL]

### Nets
GND: C29.1 C30.1 IC7.8(GND) IC7.13(G) IC8.8(GND) IC8.13(G) ; also sheet 1,2,3,4,5,6,7,8,11,12,13,14,15,16,17,18
ML1: M1.9(R1) M2.9(R1) Q6.3(C)
ML2: M1.14(R2) M2.14(R2) Q7.3(C)
ML3: M1.8(R3) M2.8(R3) Q8.3(C)
ML4: M1.12(R4) M2.12(R4) Q9.3(C)
ML5: M1.1(R5) M2.1(R5) Q10.3(C)
ML6: M1.7(R6) M2.7(R6) Q11.3(C)
ML7: M1.2(R7) M2.2(R7) Q12.3(C)
ML8: M1.5(R8) M2.5(R8) Q13.3(C)
N$1: IC7.7(QH) R49.2
N$162: IC8.7(QH) R57.2
N$163: IC8.6(QG) R58.2
N$164: IC8.4(QE) R60.2
N$165: IC8.3(QD) R61.2
N$166: IC8.2(QC) R62.2
N$167: IC8.1(QB) R63.2
N$168: IC8.15(QA) R64.2
N$169: IC8.5(QF) R59.2
N$170: IC7.6(QG) R50.2
N$171: IC7.4(QE) R52.2
N$172: IC7.3(QD) R53.2
N$173: IC7.2(QC) R54.2
N$174: IC7.1(QB) R55.2
N$175: IC7.15(QA) R56.2
N$176: IC7.5(QF) R51.2
N$177: M1.13(C1) R49.1
N$178: Q6.2(B) R47.2
N$179: Q7.2(B) R48.2
N$180: Q8.2(B) R65.2
N$181: Q9.2(B) R66.2
N$182: Q10.2(B) R67.2
N$183: Q11.2(B) R68.2
N$184: Q12.2(B) R69.2
N$185: Q13.2(B) R70.2
N$193: M1.3(C2) R50.1
N$194: M1.4(C3) R51.1
N$195: M1.10(C4) R52.1
N$196: M1.6(C5) R53.1
N$197: M1.11(C6) R54.1
N$198: M1.15(C7) R55.1
N$199: M1.16(C8) R56.1
N$200: M2.13(C1) R57.1
N$201: M2.3(C2) R58.1
N$202: M2.4(C3) R59.1
N$203: M2.10(C4) R60.1
N$204: M2.6(C5) R61.1
N$205: M2.11(C6) R62.1
N$206: M2.15(C7) R63.1
N$207: M2.16(C8) R64.1
N$272: R47.1 S35.1
N$273: R70.1 S35.8
N$274: R69.1 S35.7
N$275: R48.1 S35.2
N$283: R65.1 S35.3
N$284: R68.1 S35.6
N$285: R67.1 S35.5
N$286: R66.1 S35.4
P33: IC7.11(SCK) IC7.12(RCK) IC8.11(SCK) IC8.12(RCK) ; also sheet 1,17
P34: IC7.14(SER) ; also sheet 1,17
P35: S35.16 ; also sheet 1,4,13
P36: S35.15 ; also sheet 1,4
P37: S35.14 ; also sheet 1,4,7
P38: S35.13 ; also sheet 1,4,7
P39: S35.12 ; also sheet 1,4,7,9
P40: S35.11 ; also sheet 1,4,7,9
P41: S35.10 ; also sheet 1,4,7,9
P42: S35.9 ; also sheet 1,4,7,9
QH: IC7.9(QH*) IC8.14(SER)
VCC: C29.2 C30.2 IC7.10(SCL) IC7.16(VCC) IC8.10(SCL) IC8.16(VCC) Q6.1(E) Q7.1(E) Q8.1(E) Q9.1(E) Q10.1(E) Q11.1(E) Q12.1(E) Q13.1(E) ; also sheet 1,2,3,4,5,6,7,8,9,11,12,13,14,15,16,17,18
Unconnected: IC8.9(QH*)

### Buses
ML[1..8],SCK,SER,QH

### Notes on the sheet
- DATA Direction

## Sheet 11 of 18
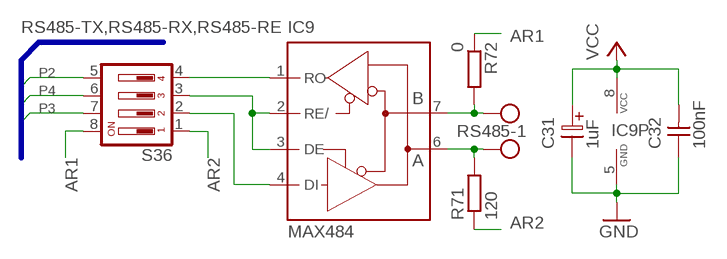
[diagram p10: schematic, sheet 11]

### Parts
C31  1uF  ELC2.5  [ELC2.5]
C32  100nF  CAP2.5  [CAP2.5]
IC9  MAX484  MAX485  [DIL8R]
R71  120  RESISTOR-10M  [R-10]
R72  0  RESISTOR-10M  [R-10]
RS485  AK500/2  [AK500/2]
S36  DIP04YL  [DIP04YL]

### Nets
AR1: R72.1 S36.8
AR2: R71.1 S36.1
AR11: IC9.7(B) R72.2 RS485.1
GND: C31.2 C32.1 IC9.5(GND) ; also sheet 1,2,3,4,5,6,7,8,10,12,13,14,15,16,17,18
N$228: IC9.6(A) R71.2 RS485.2
N$233: IC9.2(RE/) IC9.3(DE) S36.3
N$234: IC9.4(DI) S36.2
N$235: IC9.1(RO) S36.4
P2: S36.5 ; also sheet 1,4,6,12
P3: S36.7 ; also sheet 1,4,6,12
P4: S36.6 ; also sheet 1,4,6,12
VCC: C31.1 C32.2 IC9.8(VCC) ; also sheet 1,2,3,4,5,6,7,8,9,10,12,13,14,15,16,17,18

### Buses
RS485-TX,RS485-RX,RS485-RE

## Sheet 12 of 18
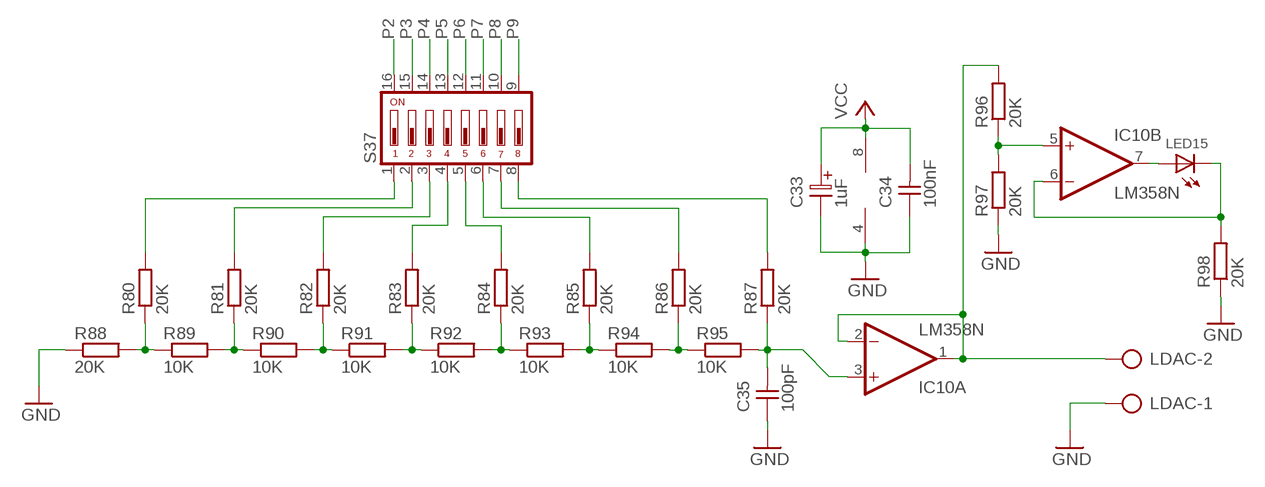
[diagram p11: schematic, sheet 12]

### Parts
C33  1uF  ELC2.5  [ELC2.5]
C34  100nF  CAP2.5  [CAP2.5]
C35  100pF  CAP2.5  [CAP2.5]
IC10  LM358N  [DIL08]
LDAC  AK500/2  [AK500/2]
LED15  LED3  [LED3MM]
R80  20K  RESISTOR-8M  [R-8]
R81  20K  RESISTOR-8M  [R-8]
R82  20K  RESISTOR-8M  [R-8]
R83  20K  RESISTOR-8M  [R-8]
R84  20K  RESISTOR-8M  [R-8]
R85  20K  RESISTOR-8M  [R-8]
R86  20K  RESISTOR-8M  [R-8]
R87  20K  RESISTOR-8M  [R-8]
R88  20K  RESISTOR-8M  [R-8]
R89  10K  RESISTOR-8M  [R-8]
R90  10K  RESISTOR-8M  [R-8]
R91  10K  RESISTOR-8M  [R-8]
R92  10K  RESISTOR-8M  [R-8]
R93  10K  RESISTOR-8M  [R-8]
R94  10K  RESISTOR-8M  [R-8]
R95  10K  RESISTOR-8M  [R-8]
R96  20K  RESISTOR-8M  [R-8]
R97  20K  RESISTOR-8M  [R-8]
R98  20K  RESISTOR-8M  [R-8]
S37  DIP08YL  [DIP08YL]

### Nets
GND: C33.2 C34.1 C35.1 IC10.4(P:V-) LDAC.1 R88.1 R97.1 R98.1 ; also sheet 1,2,3,4,5,6,7,8,10,11,13,14,15,16,17,18
N$208: R80.1 R88.2 R89.1
N$209: R81.1 R89.2 R90.1
N$210: R82.1 R90.2 R91.1
N$211: R83.1 R91.2 R92.1
N$212: R84.1 R92.2 R93.1
N$213: R85.1 R93.2 R94.1
N$214: R86.1 R94.2 R95.1
N$215: C35.2 IC10.3(A:+IN) R87.1 R95.2
N$216: R80.2 S37.1
N$217: R81.2 S37.2
N$218: R82.2 S37.3
N$219: R83.2 S37.4
N$220: R84.2 S37.5
N$221: R85.2 S37.6
N$222: R86.2 S37.7
N$223: R87.2 S37.8
N$224: IC10.1(A:OUT) IC10.2(A:-IN) LDAC.2 R96.2
N$225: IC10.5(B:+IN) R96.1 R97.2
N$226: IC10.6(B:-IN) LED15.K(C) R98.2
N$227: IC10.7(B:OUT) LED15.A
P2: S37.16 ; also sheet 1,4,6,11
P3: S37.15 ; also sheet 1,4,6,11
P4: S37.14 ; also sheet 1,4,6,11
P5: S37.13 ; also sheet 1,4,6,18
P6: S37.12 ; also sheet 1,4,5
P7: S37.11 ; also sheet 1,4,5
P8: S37.10 ; also sheet 1,4,5
P9: S37.9 ; also sheet 1,4,5
VCC: C33.1 C34.2 IC10.8(P:V+) ; also sheet 1,2,3,4,5,6,7,8,9,10,11,13,14,15,16,17,18

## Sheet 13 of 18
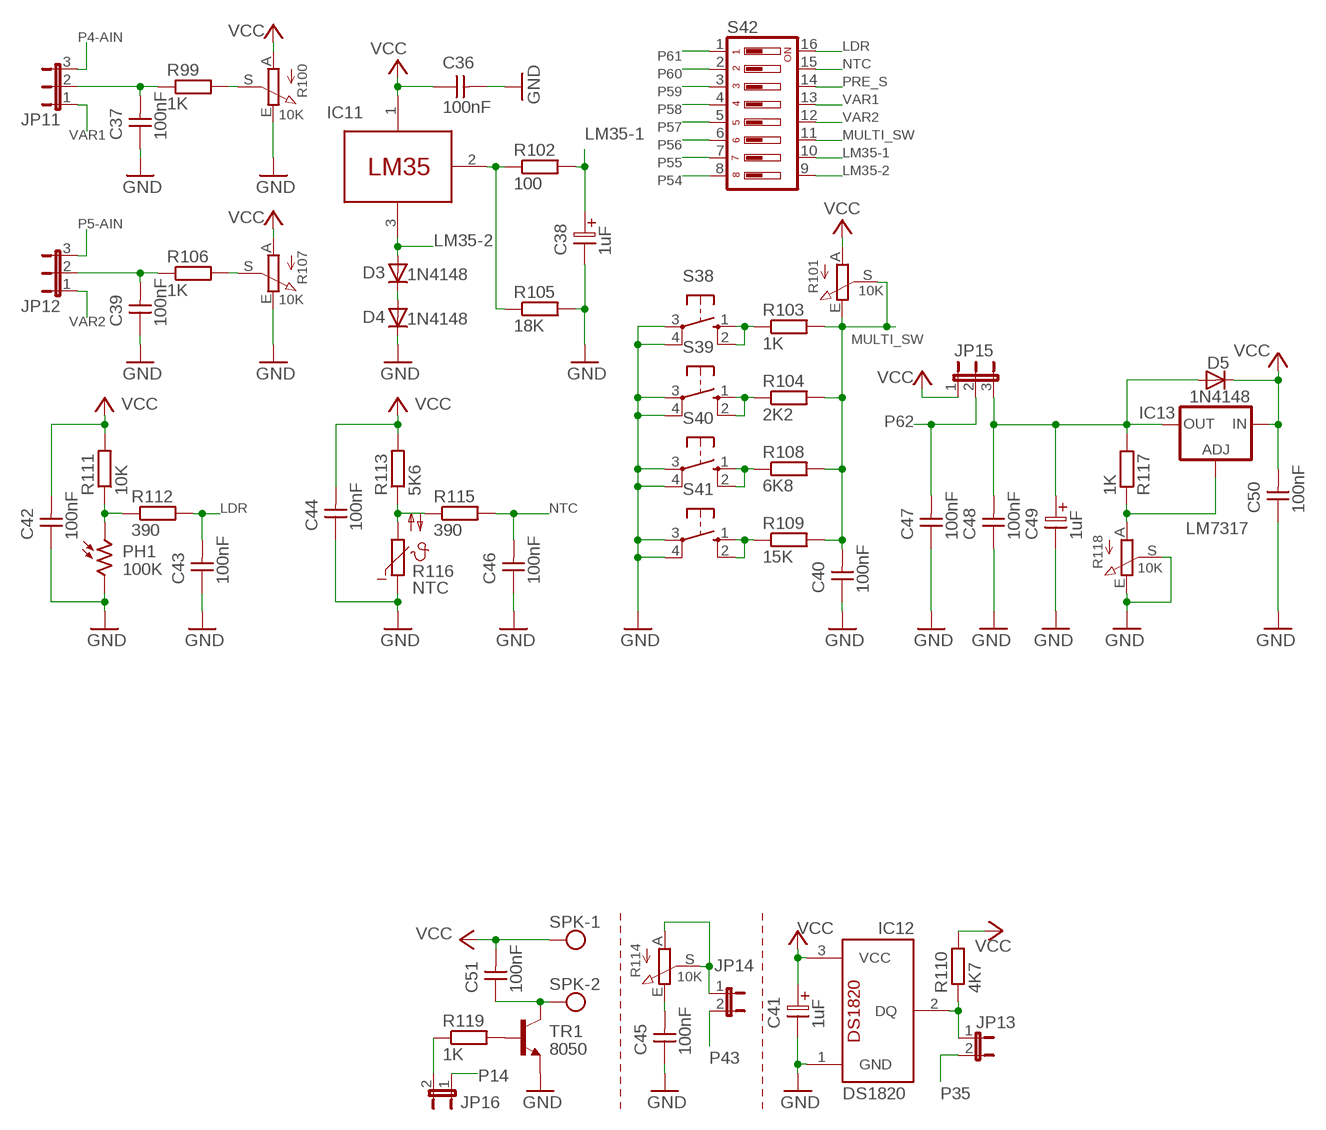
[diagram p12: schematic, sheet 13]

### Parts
C36  100nF  CAP2.5  [CAP2.5]
C37  100nF  CAP2.5  [CAP2.5]
C38  1uF  ELC2.5  [ELC2.5]
C39  100nF  CAP2.5  [CAP2.5]
C40  100nF  CAP2.5  [CAP2.5]
C41  1uF  ELC2.5  [ELC2.5]
C42  100nF  CAP2.5  [CAP2.5]
C43  100nF  CAP2.5  [CAP2.5]
C44  100nF  CAP2.5  [CAP2.5]
C45  100nF  CAP5  [CAP5]
C46  100nF  CAP2.5  [CAP2.5]
C47  100nF  CAP2.5  [CAP2.5]
C48  100nF  CAP2.5  [CAP2.5]
C49  1uF  ELC2.5  [ELC2.5]
C50  100nF  CAP2.5  [CAP2.5]
C51  100nF  CAP2.5  [CAP2.5]
D3  1N4148  1N4148-7  [DO35-7]
D4  1N4148  1N4148-7  [DO35-7]
D5  1N4148  [DO35-10]
IC11  LM35  [LM35]
IC12  DS1820  [TO92L]
IC13  LM7317  LM317TL  [317TL]
JP11  JP2E  [JP2]
JP12  JP2E  [JP2]
JP13  JP1EY  [JP1Y]
JP14  JP1EY  [JP1Y]
JP15  JP2E  [JP2]
JP16  JP1EY  [JP1Y]
PH1  100K  V1060_32  [TO-5_V10]
R99  1K  RESISTOR-10M  [R-10]
R100  10K  POT  [POT]
R101  10K  POT  [POT]
R102  100  RESISTOR-10M  [R-10]
R103  1K  RESISTOR-7M  [R-7]
R104  2K2  RESISTOR-7M  [R-7]
R105  18K  RESISTOR-10M  [R-10]
R106  1K  RESISTOR-10M  [R-10]
R107  10K  POT  [POT]
R108  6K8  RESISTOR-7M  [R-7]
R109  15K  RESISTOR-7M  [R-7]
R110  4K7  RESISTOR-10M  [R-10]
R111  10K  RESISTOR-10M  [R-10]
R112  390  RESISTOR-10M  [R-10]
R113  5K6  RESISTOR-10M  [R-10]
R114  10K  POT  [POT]
R115  390  RESISTOR-10M  [R-10]
R116  NTC  B57164  [B57164]
R117  1K  RESISTOR-10M  [R-10]
R118  10K  POT  [POT]
R119  1K  RESISTOR-10M  [R-10]
S38  TAC_SW_M  [B3F-10XX]
S39  TAC_SW_M  [B3F-10XX]
S40  TAC_SW_M  [B3F-10XX]
S41  TAC_SW_M  [B3F-10XX]
S42  DIP08YL  [DIP08YL]
SPK  AK500/2  [AK500/2]
TR1  8050  [TO92L]

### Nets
GETRC: JP14.1 R114.A R114.S
GND: C36.2 C37.1 C38.2 C39.1 C40.1 C41.2 C42.1 C43.1 C44.1 C45.1 C46.1 C47.1 C48.1 C49.2 C50.1 D4.C IC12.1(GND) PH1.2 R100.E R105.2 R107.E R116.1 R118.E R118.S S38.3(P) S38.4(P1) S39.3(P) S39.4(P1) S40.3(P) S40.4(P1) S41.3(P) S41.4(P1) TR1.1(E) ; also sheet 1,2,3,4,5,6,7,8,10,11,12,14,15,16,17,18
LDR: C43.2 R112.2 S42.16
LM35-1: C38.1 R102.2 S42.10
LM35-2: D3.A IC11.3(GND) S42.9
MULTI_SW: C40.2 R101.E R101.S R103.2 R104.2 R108.2 R109.2 S42.11
N$129: IC11.2(VO) R102.1 R105.1
N$130: D3.C D4.A
N$137: IC12.2(DQ) JP13.1 R110.1
N$146: R99.2 R100.S
N$147: R106.2 R107.S
N$148: C37.2 JP11.2 R99.1
N$149: C39.2 JP12.2 R106.1
N$151: PH1.1 R111.1 R112.1
N$152: R104.1 S39.1(S) S39.2(S1)
N$153: R108.1 S40.1(S) S40.2(S1)
N$154: R109.1 S41.1(S) S41.2(S1)
N$155: C51.1 SPK.2 TR1.3(C)
N$156: R103.1 S38.1(S) S38.2(S1)
N$157: JP16.2 R119.1
N$158: R113.1 R115.1 R116.2
N$159: R119.2 TR1.2(B)
N$160: C48.2 C49.1 D5.A IC13.2(OUT) JP15.3 R117.2
N$161: IC13.1(ADJ) R117.1 R118.A
N$236: C45.2 R114.E
NTC: C46.2 R115.2 S42.15
P4-AIN: JP11.3
P5-AIN: JP12.3
P14: JP16.1 ; also sheet 1,4,5
P35: JP13.2 ; also sheet 1,4,10
P43: JP14.2 ; also sheet 1,16
P54: S42.8 ; also sheet 1,4
P55: S42.7 ; also sheet 1,4
P56: S42.6 ; also sheet 1,4
P57: S42.5 ; also sheet 1,4
P58: S42.4 ; also sheet 1,4
P59: S42.3 ; also sheet 1,4
P60: S42.2 ; also sheet 1,4
P61: S42.1 ; also sheet 1,4
P62: C47.2 JP15.2 ; also sheet 1
PRE_S: S42.14 ; also sheet 14
VAR1: JP11.1 S42.13
VAR2: JP12.1 S42.12
VCC: C36.1 C41.1 C42.2 C44.2 C50.2 C51.2 D5.C IC11.1(VCC) IC12.3(VCC) IC13.3(IN) JP15.1 R100.A R101.A R107.A R110.2 R111.2 R113.2 SPK.1 ; also sheet 1,2,3,4,5,6,7,8,9,10,11,12,14,15,16,17,18

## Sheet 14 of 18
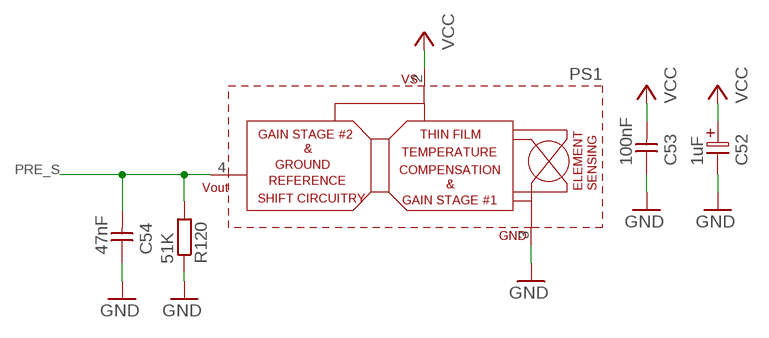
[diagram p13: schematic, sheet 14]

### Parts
C52  1uF  ELC2.5  [ELC2.5]
C53  100nF  CAP2.5  [CAP2.5]
C54  47nF  CAP2.5  [CAP2.5]
PS1  MPXAZ6115A  [MPXAZ6115A]
R120  51K  RESISTOR-10M  [R-10]

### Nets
GND: C52.2 C53.1 C54.1 PS1.3(GND) R120.1 ; also sheet 1,2,3,4,5,6,7,8,10,11,12,13,15,16,17,18
PRE_S: C54.2 PS1.4(VO) R120.2 ; also sheet 13
VCC: C52.1 C53.2 PS1.2(VS) ; also sheet 1,2,3,4,5,6,7,8,9,10,11,12,13,15,16,17,18

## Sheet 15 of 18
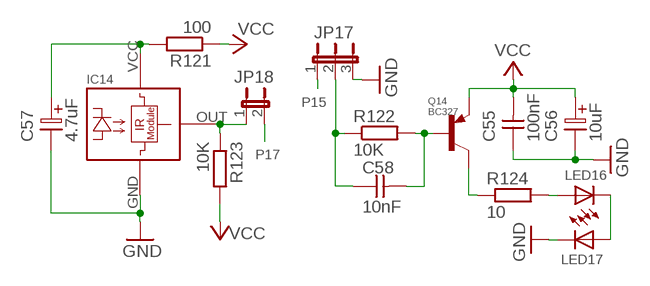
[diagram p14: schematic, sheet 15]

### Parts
C55  100nF  CAP2.5  [CAP2.5]
C56  10uF  ELC2.5  [ELC2.5]
C57  4.7uF  ELC2.5  [ELC2.5]
C58  10nF  CAP2.5  [CAP2.5]
IC14  IR-RECEIVERIR  [IR-RECEIVER]
JP17  JP2E  [JP2]
JP18  JP1EY  [JP1Y]
LED16  LED5  [LED5MM]
LED17  LED5  [LED5MM]
Q14  BC327  BC327L  [TO92L]
R121  100  RESISTOR-7M  [R-7]
R122  10K  RESISTOR-7M  [R-7]
R123  10K  RESISTOR-7M  [R-7]
R124  10  RESISTOR-7M  [R-7]

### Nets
+VIR: C57.1 IC14.VCC R121.2
ASAS: C58.1 JP17.2 R122.1
GND: C55.1 C56.2 C57.2 IC14.GND JP17.3 LED17.K(C) ; also sheet 1,2,3,4,5,6,7,8,10,11,12,13,14,16,17,18
IR: IC14.OUT JP18.1 R123.1
N$133: C58.2 Q14.2(B) R122.2
N$134: LED16.A R124.2
N$135: Q14.3(C) R124.1
N$136: LED16.K(C) LED17.A
P15: JP17.1 ; also sheet 1,4,5
P17: JP18.2 ; also sheet 1,4,5
VCC: C55.2 C56.1 Q14.1(E) R121.1 R123.2 ; also sheet 1,2,3,4,5,6,7,8,9,10,11,12,13,14,16,17,18

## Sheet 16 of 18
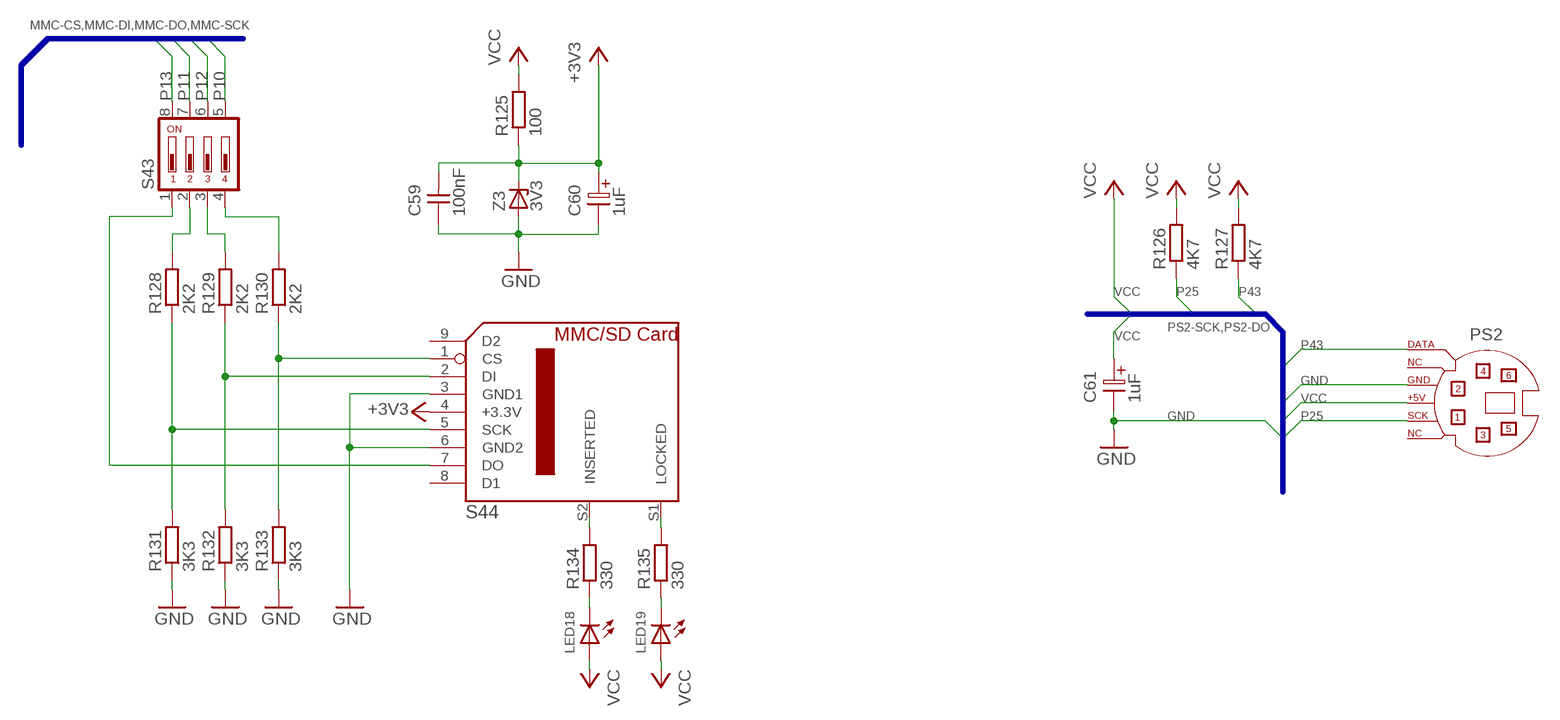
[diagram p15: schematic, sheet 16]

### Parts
C59  100nF  CAP2.5  [CAP2.5]
C60  1uF  ELC2.5  [ELC2.5]
C61  1uF  ELC2.5  [ELC2.5]
LED18  LED3  [LED3MM]
LED19  LED3  [LED3MM]
PS2  PS2-CON  [PS2-CON]
R125  100  RESISTOR-10M  [R-10]
R126  4K7  RESISTOR-10M  [R-10]
R127  4K7  RESISTOR-10M  [R-10]
R128  2K2  RESISTOR-7M  [R-7]
R129  2K2  RESISTOR-10M  [R-10]
R130  2K2  RESISTOR-10M  [R-10]
R131  3K3  RESISTOR-10M  [R-10]
R132  3K3  RESISTOR-10M  [R-10]
R133  3K3  RESISTOR-7M  [R-7]
R134  330  RESISTOR-7M  [R-7]
R135  330  RESISTOR-7M  [R-7]
S43  DIP04YL  [DIP04YL]
S44  MMC-SD-CARDP  [MMC-SD-CARD-P]
Z3  3V3  ZENER12  [SOD120]

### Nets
+3V3: C59.2 C60.1 R125.1 S44.4(+3.3V) Z3.C
GND: C59.1 C60.2 C61.2 PS2.3 R131.1 R132.1 R133.1 S44.3(GND1) S44.6(GND2) Z3.A ; also sheet 1,2,3,4,5,6,7,8,10,11,12,13,14,15,17,18
N$98: R134.2 S44.S2(INSERTED)
N$99: LED18.K(C) R134.1
N$100: R135.2 S44.S1(LOCKED)
N$101: LED19.K(C) R135.1
N$102: R128.1 R131.2 S44.5(SCK)
N$103: R129.1 R132.2 S44.2(DI)
N$104: R130.1 R133.2 S44.1(CS)
N$105: S43.1 S44.7(DO)
N$107: R130.2 S43.4
N$108: R129.2 S43.3
N$109: R128.2 S43.2
P10: S43.5 ; also sheet 1,4,5
P11: S43.7 ; also sheet 1,3,4,5
P12: S43.6 ; also sheet 1,3,4,5
P13: S43.8 ; also sheet 1,3,4,5
P25: PS2.5 R126.1 ; also sheet 1,4,5,8
P43: PS2.1 R127.1 ; also sheet 1,13
VCC: C61.1 LED18.A LED19.A PS2.4 R125.2 R126.2 R127.2 ; also sheet 1,2,3,4,5,6,7,8,9,10,11,12,13,14,15,17,18
Unconnected: PS2.2 PS2.6 S44.8(D1) S44.9(D2)

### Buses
MMC-CS,MMC-DI,MMC-DO,MMC-SCK
PS2-SCK,PS2-DO

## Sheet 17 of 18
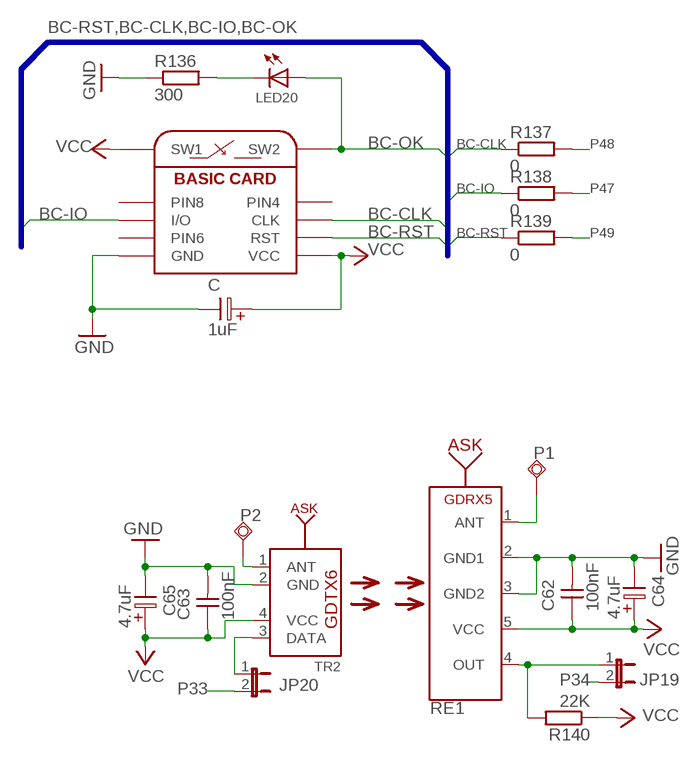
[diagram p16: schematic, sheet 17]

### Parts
C  1uF  ELC2.5  [ELC2.5]
C62  100nF  CAP2.5  [CAP2.5]
C63  100nF  CAP2.5  [CAP2.5]
C64  4.7uF  ELC2.5  [ELC2.5]
C65  4.7uF  ELC2.5  [ELC2.5]
JP19  JP1EY  [JP1Y]
JP20  JP1EY  [JP1Y]
LED20  LED3  [LED3MM]
P1  PADX  [PAD1]
P2  PADX  [PAD1]
R136  300  RESISTOR-10M  [R-10]
R137  0  RESISTOR-13M  [R-13]
R138  0  RESISTOR-15M  [R-15]
R139  0  RESISTOR-12M  [R-12]
R140  22K  RESISTOR-10M  [R-10]
RE1  GDRX5-ASK  [GDRX5]
TR2  GDTX6-ASK  [GDTX6]
U$1  SMARTCARD  [CARDSOCKET]

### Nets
BC-CLK: R137.1 U$1.CLK
BC-IO: R138.1 U$1.I/O
BC-OK: LED20.A U$1.SW2
BC-RST: R139.1 U$1.RST
GND: C62.2 C63.2 C64.2 C65.2 C.2 R136.1 RE1.2(GND1) RE1.3(GND2) TR2.2(GND) U$1.GND ; also sheet 1,2,3,4,5,6,7,8,10,11,12,13,14,15,16,18
N$186: P2.1(TP) TR2.1(ANT)
N$187: LED20.K(C) R136.2
N$188: P1.1(TP) RE1.1(ANT)
N$190: JP19.1 R140.2 RE1.4(OUT)
N$191: JP20.1 TR2.3(DATA)
P33: JP20.2 ; also sheet 1,10
P34: JP19.2 ; also sheet 1,10
P47: R138.2 ; also sheet 1,4,7,9
P48: R137.2 ; also sheet 1,4,7,9
P49: R139.2 ; also sheet 1,4,7,9
VCC: C62.1 C63.1 C64.1 C65.1 C.1 R140.1 RE1.5(VCC) TR2.4(VCC) U$1.SW1 U$1.VCC ; also sheet 1,2,3,4,5,6,7,8,9,10,11,12,13,14,15,16,18
Unconnected: U$1.PIN4 U$1.PIN6 U$1.PIN8

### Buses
BC-RST,BC-CLK,BC-IO,BC-OK

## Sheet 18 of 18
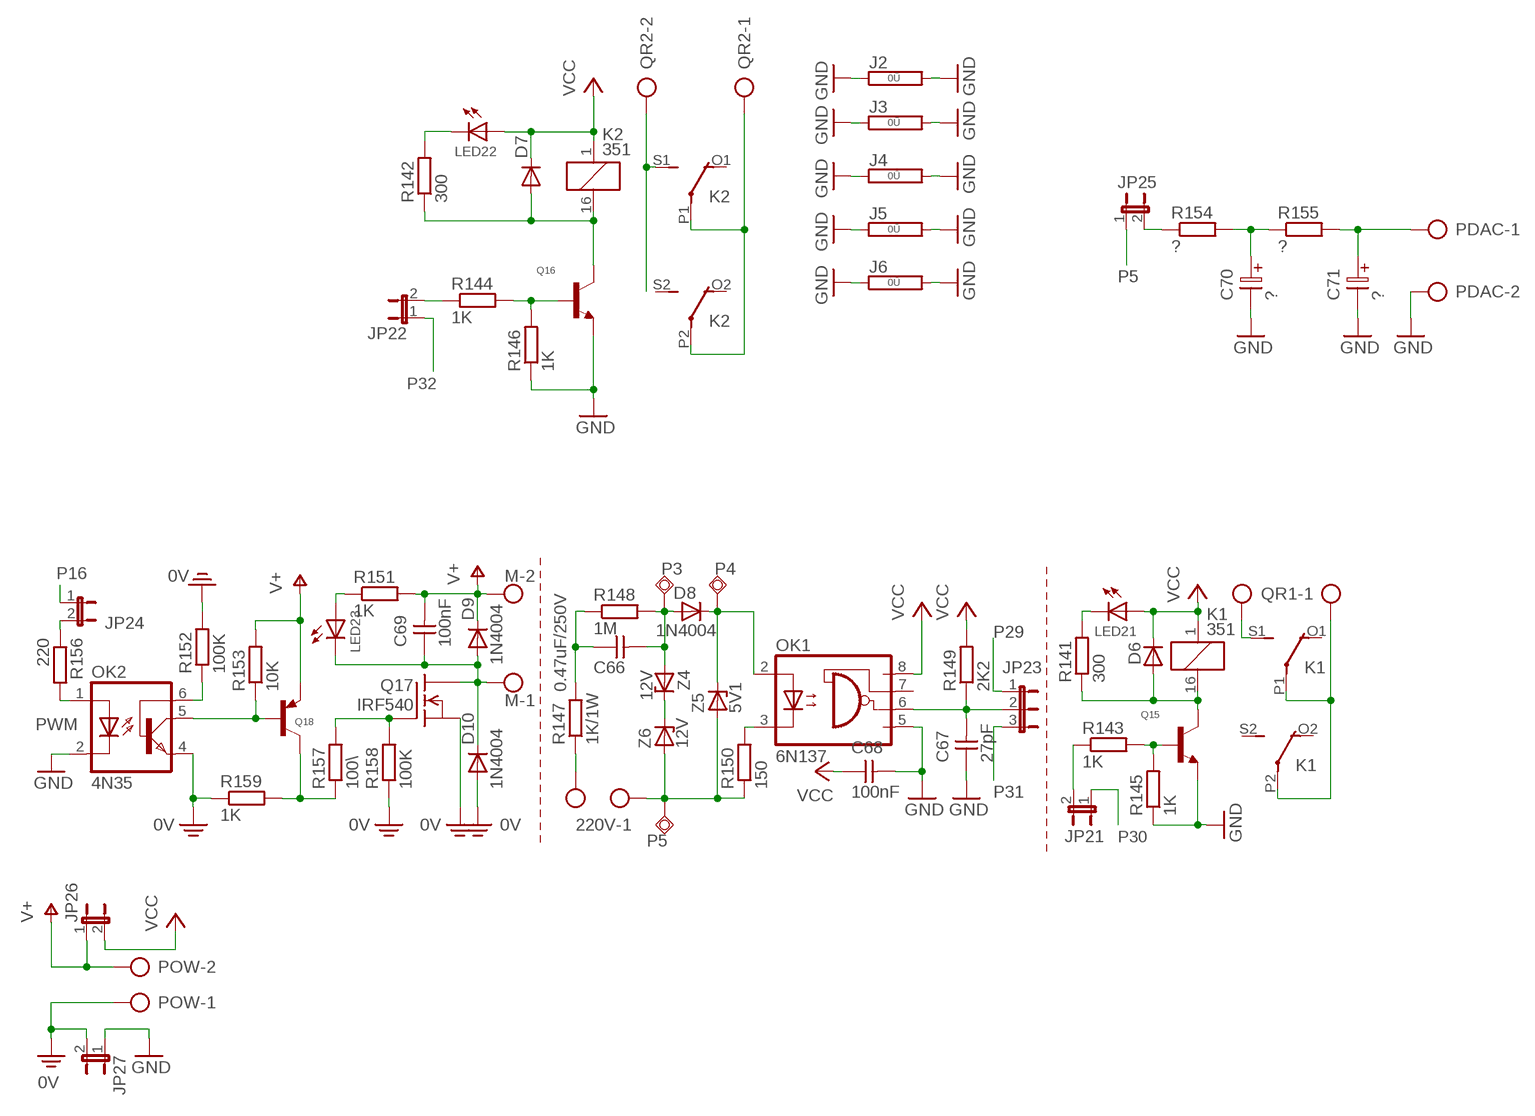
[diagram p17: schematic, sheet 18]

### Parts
220V  AK500/2  [AK500/2]
C66  0.47uF/250V  CAP10BS  [CXXC10BS]
C67  27pF  CAP2.5  [CAP2.5]
C68  100nF  CAP2.5  [CAP2.5]
C69  100nF  CAP7BS  [CXXC7BS]
C70  ?  ELC2.5  [ELC2.5]
C71  ?  ELC2.5  [ELC2.5]
D6  1N4148-7  [DO35-7]
D7  1N4148-7  [DO35-7]
D8  1N4004  [DO41-10]
D9  1N4004  [DO41-10]
D10  1N4004  [DO41-10]
J2  0R5  [05]
J3  0R7  [07]
J4  0R5  [05]
J5  0R5  [05]
J6  0R5  [05]
JP21  JP1EY  [JP1Y]
JP22  JP1EY  [JP1Y]
JP23  JP2E  [JP2]
JP24  JP1EY  [JP1Y]
JP25  JP1EY  [JP1Y]
JP26  JP1E  [JP1]
JP27  JP1E  [JP1]
K1  351  [351]
K2  351  [351]
LED21  LED3  [LED3MM]
LED22  LED3  [LED3MM]
LED23  LED3  [LED3MM]
M  AK500/2  [AK500/2]
OK1  6N137  [DIL08]
OK2  4N35  [DIL06]
P3  PADB  [PAD0]
P4  PADB  [PAD0]
P5  PADB  [PAD0]
PDAC  AK500/2  [AK500/2]
POW  AK500/2  [AK500/2]
Q15  BC337L  [TO92L]
Q16  BC337L  [TO92L]
Q17  IRF540  [TO220]
Q18  BC327L  [TO92L]
QR1  AK500/2  [AK500/2]
QR2  AK500/2  [AK500/2]
R141  300  RESISTOR-10M  [R-10]
R142  300  RESISTOR-10M  [R-10]
R143  1K  RESISTOR-7M  [R-7]
R144  1K  RESISTOR-7M  [R-7]
R145  1K  RESISTOR-7M  [R-7]
R146  1K  RESISTOR-7M  [R-7]
R147  1K/1W  RESISTOR-10M  [R-10]
R148  1M  RESISTOR-10M  [R-10]
R149  2K2  RESISTOR-7M  [R-7]
R150  150  RESISTOR-10M  [R-10]
R151  1K  RESISTOR-7M  [R-7]
R152  100K  RESISTOR-10M  [R-10]
R153  10K  RESISTOR-10M  [R-10]
R154  ?  RESISTOR-10M  [R-10]
R155  ?  RESISTOR-10M  [R-10]
R156  220  RESISTOR-7M  [R-7]
R157  100\  RESISTOR-10M  [R-10]
R158  100K  RESISTOR-8M  [R-8]
R159  1K  RESISTOR-10M  [R-10]
Z4  12V  ZENER  [SOD81]
Z5  5V1  ZENER  [SOD81]
Z6  12V  ZENER  [SOD81]

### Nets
GND: C67.1 C68.2 C70.2 C71.2 J2.1 J2.2 J3.1 J3.2 J4.1 J4.2 J5.1 J5.2 J6.1 J6.2 JP27.1 OK1.5(GND) OK2.2(C) PDAC.2 Q15.3(E) Q16.3(E) R145.1 R146.1 ; also sheet 1,2,3,4,5,6,7,8,10,11,12,13,14,15,16,17
GROUP-A1: JP21.2 R143.1
GROUP-A2: JP22.2 R144.1
N$150: C70.1 R154.2 R155.1
N$231: C71.1 PDAC.1 R155.2
N$232: JP25.2 R154.1
N$238: Q15.1(B) R143.2 R145.2
N$239: LED21.K(C) R141.2
N$240: D6.A K1.16 Q15.2(C) R141.1
N$241: K1.S1(2:S) QR1.2
N$242: Q16.1(B) R144.2 R146.2
N$243: LED22.K(C) R142.2
N$244: D7.A K2.16 Q16.2(C) R142.1
N$245: K2.S1(2:S) QR2.2
N$246: OK2.5(COL) Q18.2(B) R153.1
N$247: Q17.1(G) R157.2 R158.2
N$248: OK2.1(A) R156.2
N$249: C69.1 D9.A D10.C LED23.K(C) M.1 Q17.2(D)
N$250: LED23.A R151.1
N$251: OK2.6(BAS) R152.1
N$252: Q18.3(C) R157.1 R159.2
N$253: 220V.1 R147.1
N$254: K1.P1(2:P) K1.P2(3:P) QR1.1
N$255: C66.1 R147.2 R148.1
N$256: K2.P1(2:P) K2.P2(3:P) QR2.1
N$257: C66.2 D8.A P3.1(TP) R148.2 Z4.A
N$258: 220V.2 P5.1(TP) R150.1 Z5.A Z6.A
N$259: OK1.3(C) R150.2
N$260: D8.C OK1.2(A) P4.1(TP) Z5.C
N$262: Z4.C Z6.C
P5: JP25.1 ; also sheet 1,4,6,12
P16: JP24.1 ; also sheet 1,4,5
P29: JP23.1 ; also sheet 1,4
P30: JP21.1 ; also sheet 1,4
P31: JP23.3 ; also sheet 1,4
P32: JP22.1 ; also sheet 1,4
PE: D10.A JP27.2 OK2.4(EMI) POW.1 Q17.3(S) R152.2 R158.1 R159.1 ; supply symbol labelled 0V
PULS: C67.2 JP23.2 OK1.6(VO) R149.1
PWM: JP24.2 R156.1
V+: C69.2 D9.C JP26.1 M.2 POW.2 Q18.1(E) R151.2 R153.2
VCC: C68.1 D6.C D7.C JP26.2 K1.1 K2.1 LED21.A LED22.A OK1.8(VCC) R149.2 ; also sheet 1,2,3,4,5,6,7,8,9,10,11,12,13,14,15,16,17
Unconnected: K1.O1(2:O) K1.O2(3:O) K1.S2(3:S) K2.O1(2:O) K2.O2(3:O) K2.S2(3:S) OK1.7(VE)

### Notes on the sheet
- 1 | 2

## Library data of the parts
220V LDAC M PDAC POW PWR1-PWR4 QR1 QR2 RS485 SPK = WALID2008A:AK500/2: CONNECTOR
B1 = WALID2008A:RB1A: RECTIFIER 1 A
B2 = WALID2006:BATT
C C1-C5 C7 C8 C11 C15-C25 C27 C31 C33 C38 C41 C49 C52 C56 C57 C60 C61 C64 C65 C70 C71 = WALID2008A:ELC: Electric Capacitor
C6 C9 C10 C12-C14 C26 C28-C30 C32 C34-C37 C39 C40 C42-C48 C50 C51 C53-C55 C58 C59 C62 C63 C66-C69 = WALID2008A:CAP: Ceramic Capacitor
COM1 COM2 = WALID2008A:F09HP: SUB-D
D1 D8-D10 = WALID2008A:1N4004: DIODE
D2-D7 = WALID2008A:1N4148: DIODE
DSP1 = WALID2008A:DISPLAY-Q0.56': LED DISPLAY 1-character 7 segment, decimal point right
GLCD = WALID2008A:LCD128X64: HDM64GS12 128 X 64 Dots Graphic Source: http://www.hantronix.com/down/64gs12-r.pdf
IC1 = WALID2008A:78XXL: VOLTAGE REGULATOR
IC2 = WALID2008A:74*244: Octal BUFFER and LINE DRIVER, 3-state
IC3 IC4 = WALID2008A:MAX232: RS232 TRANSEIVER
IC5 = WALID2008A:AT24C*: 2-wire serial EEPROM
IC6 = WALID2008A:DS1307
IC7 IC8 = WALID2008A:74HC595
IC9 = WALID2008A:MAX485: RS485 TRANSEIVER
IC10 = linear:LM358: OP AMP also LM158; LM258; LM2904 Source: http://cache.national.com/ds/LM/LM158.pdf
IC11 = WALID2008A:LM35: Temperature Sensor
IC12 = WALID2008A:DS1820: 1?WireTM Digital Thermometer
IC13 = WALID2008A:LM317TL: VOLTAGE REGULATOR
IC14 = WALID2008A:IR-RECEIVER: IR Receiver
J1 = jumper:J: Bridge
J2-J6 = WALID2008A:0R: Bridge 0R 10mm
JP1-JP6 JP8 JP11 JP12 JP15 JP17 JP23 = jumper:JP2E: JUMPER
JP7 JP9 JP10 JP13 JP14 JP16 JP18-JP22 JP24-JP27 = jumper:JP1E: JUMPER
K1 K2 = relay:351: RELAY 2 x switch, Omron
LCD = WALID2008A:LCD20X4: Tuxgraphics LCD display 20x2 characters reflective, without background light Source: tuxgr_20x2.pdf
LED1 LED3-LED10 LED15-LED23 = WALID2008A:LED: LED 3mm, 5mm
LED2 LED11-LED14 = led:LED: LED
LPT = WALID2008A:F25HP: SUB-D
M1 M2 = WALID2008A:8X8MATRIX-3MM: 8x8 Matrix / 3mm
OK1 = optocoupler:6N137: MOTOROLA OPTO COUPLER
OK2 = optocoupler:4N35: MOTOROLA OPTO COUPLER
P1-P5 = WALID2008A:PAD: PAD
PH1 = photo-elements:?1060*: Sensor Street Light control
PORTA PORTB PORTC PORTD PORTE PORTF = con-lsta:FE08-1: FEMALE HEADER
PS1 = WALID2008A:MPXAZ6115A: 15 to 115 kPa (2.2 to 16.7 psi) Pressure Sensor INTEGRATED PRESSURE SENSOR 0.2 to 4.8 Volts Output Media Resistant and High Temperature Accuracy Integrated Silicon Pressure Sensor for Measuring Absolute Pressure, On--Chip Signal Conditioned, Temperature Compensated and Calibrated
PS2 = WALID2008A:PS2-CON: YAMAICHI CONNECTOR
PWR = WALID2008A:DC-JACK: FEMALE PRINT CONNECTOR Niedervolt-Steckverbinder Distributor Conrad
Q1 = WALID2008A:CRYSTAL: Crystal
Q2-Q14 Q18 = WALID2008A:BC327: PNP Transistror
Q15 Q16 = WALID2008A:BC337: NPN Transistor
Q17 = transistor-fet:IRF540: N-Channel Enhancement MOSFET (HEXFET); 100V; 28A; 0,077Ohm
R1 R3-R16 R25-R28 = WALID2008A:R-5: Resistor 5, 7,8, 10, 12, 13, 15, 17, 19, 20, 25, 28, 30mm
R2 R17-R24 R31-R72 R80-R99 R102-R106 R108-R113 R115 R117 R119-R159 = WALID2008A:RESISTOR: Resistor 5, 7,8, 10, 12, 13, 15, 17, 19, 20, 25, 28, 30mm
R29 R30 R100 R101 R107 R114 R118 = WALID2008A:POT: Spain Pot Resistor
R116 = ptc-ntc:B57164: SIEMENS NTC
RE1 = WALID2008A:GDRX5-ASK: ASK RECEIVING MODULE TTL Interface GDRX5
RN1-RN5 = resistor-sil:G08R: SIL RESISTOR
RST = WALID2008A:TAC_SW_S: Open Normal Switch
S2-S6 S35 S37 S42 = switch-dil:DIP08YL: DIL/CODE SWITCH
S7 S8 S13 S14 S19 S24 S29 S30 = WALID2008A:10-XX: OMRON SWITCH
S9-S12 S15-S18 S20-S23 S25-S28 = WALID2008A:TAC_SW_B: OMRON SWITCH
S31-S34 S36 S43 = switch-dil:DIP04YL: DIL/CODE SWITCH
S38-S41 = WALID2008A:TAC_SW_M: OMRON SWITCH
S44 = WALID2008A:MMC-SD-CARD: MMC / SD Card Socket
SW1-SW3 = WALID2008A:POWER_SW: SLIDING SWITCH
TR1 = WALID2008A:8050
TR2 = WALID2008A:GDTX6-ASK: ASK TRANSMITTING MODULE GDTX6
U1 = WALID2008A:ATMEGA128_HOLDER
U$1 = WALID2008A:SMARTCARD: ISO 7816 SmartCard and CardSocket
Z1-Z6 = WALID2008A:ZENER: Z DIODE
